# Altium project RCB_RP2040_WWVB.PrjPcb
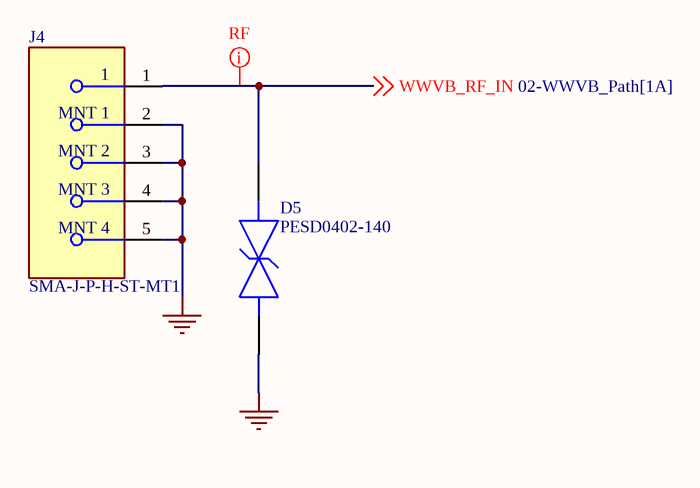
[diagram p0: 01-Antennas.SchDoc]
prjCompanyName: Meta Platforms Technologies, LLC.; prjContactAddress1: 9845 Willows Road NE; prjContactAddress2: Redmond, WA 98052; prjContactEmail: Contact Email; prjContactPhone: (...)-...-....; prjElectricalEngineer: Electical Engineer; prjElectricalEngineerEmail: Electical Engineer Email; prjLayoutEngineer: Layout Engineer; prjLayoutEngineerEmail: Layout Engineer Email; prjMechanicalEngineer: Mechanical Engineer; prjMechanicalEngineerEmail: Mechanical Engineer Email; prjPCB_IPN: 844-XXXXX-XX; prjPCB_Name: PCB Name; prjPCB_Revision: X1; prjProjectName: Project Name; prjSchematic_IPN: 846-XXXXX-XX; prjSchematic_Revision: X1; XprjPCBA_IPN: Set v_prjPCBA_IPN in variant parameters; XprjPCBA_Revision: Set v_prjPCBA_Revision in variant parameters
8 sheets, 224 parts. Net scope: global (net labels, ports and power ports of the same name join across sheets).
Board file: RCB_RP2040_WWVB_V1.PcbDoc
Sheets:
  01-Antennas.SchDoc
  02-WWVB_Path.SchDoc
  03-8A34004_DPLL-1.SchDoc
  04-8A34004_DPLL-2.SchDoc
  05-TCXO_Crystal.SchDoc
  06-RP2040.SchDoc
  07-USB-Prog.SchDoc
  08-Power.SchDoc

## Sheet 01-Antennas.SchDoc
size B; SheetNumber: 1; SheetTotal: 7; SPICEModelCacheELOCFEDZ: <root> / <DocumentId>ELOCFEDZ</DocumentId> / </root>

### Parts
D5  PESD0402-140  [FP-PESD0402-MFG]
J4  SMA-J-P-H-ST-MT1  [FP-SMA-J-P-H-ST-MT1-MFG]

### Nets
GND: D5.1 J4.2(MNT_1) J4.3(MNT_2) J4.4(MNT_3) J4.5(MNT_4)
WWVB_RF_IN: D5.2 J4.1 ; off-sheet WWVB_RF_IN

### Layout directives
net class RF: WWVB_RF_IN

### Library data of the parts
D5 = CMP-08607-000011-1: TVS DIODE 14V 40V 0402; Manufacturer: Littelfuse Inc.; Automotive Grade: Grade 1; Capacitance: 0.25pF; Value: 0.25pF; Direction: Bidirectional; Number Of Channels: 1
J4 = CMP-02754-000007-1: CONN SMA JACK STR 50 OHM SMD; Dielectric Material: PTFE; Voltage Rating: 335V; Body Material: Brass; Center Contact Plating: Gold; Impedance: 50R; Number of Ports: 1; Max Frequency: 20GHz

## Sheet 02-WWVB_Path.SchDoc
size B; SheetNumber: 2; SheetTotal: 8
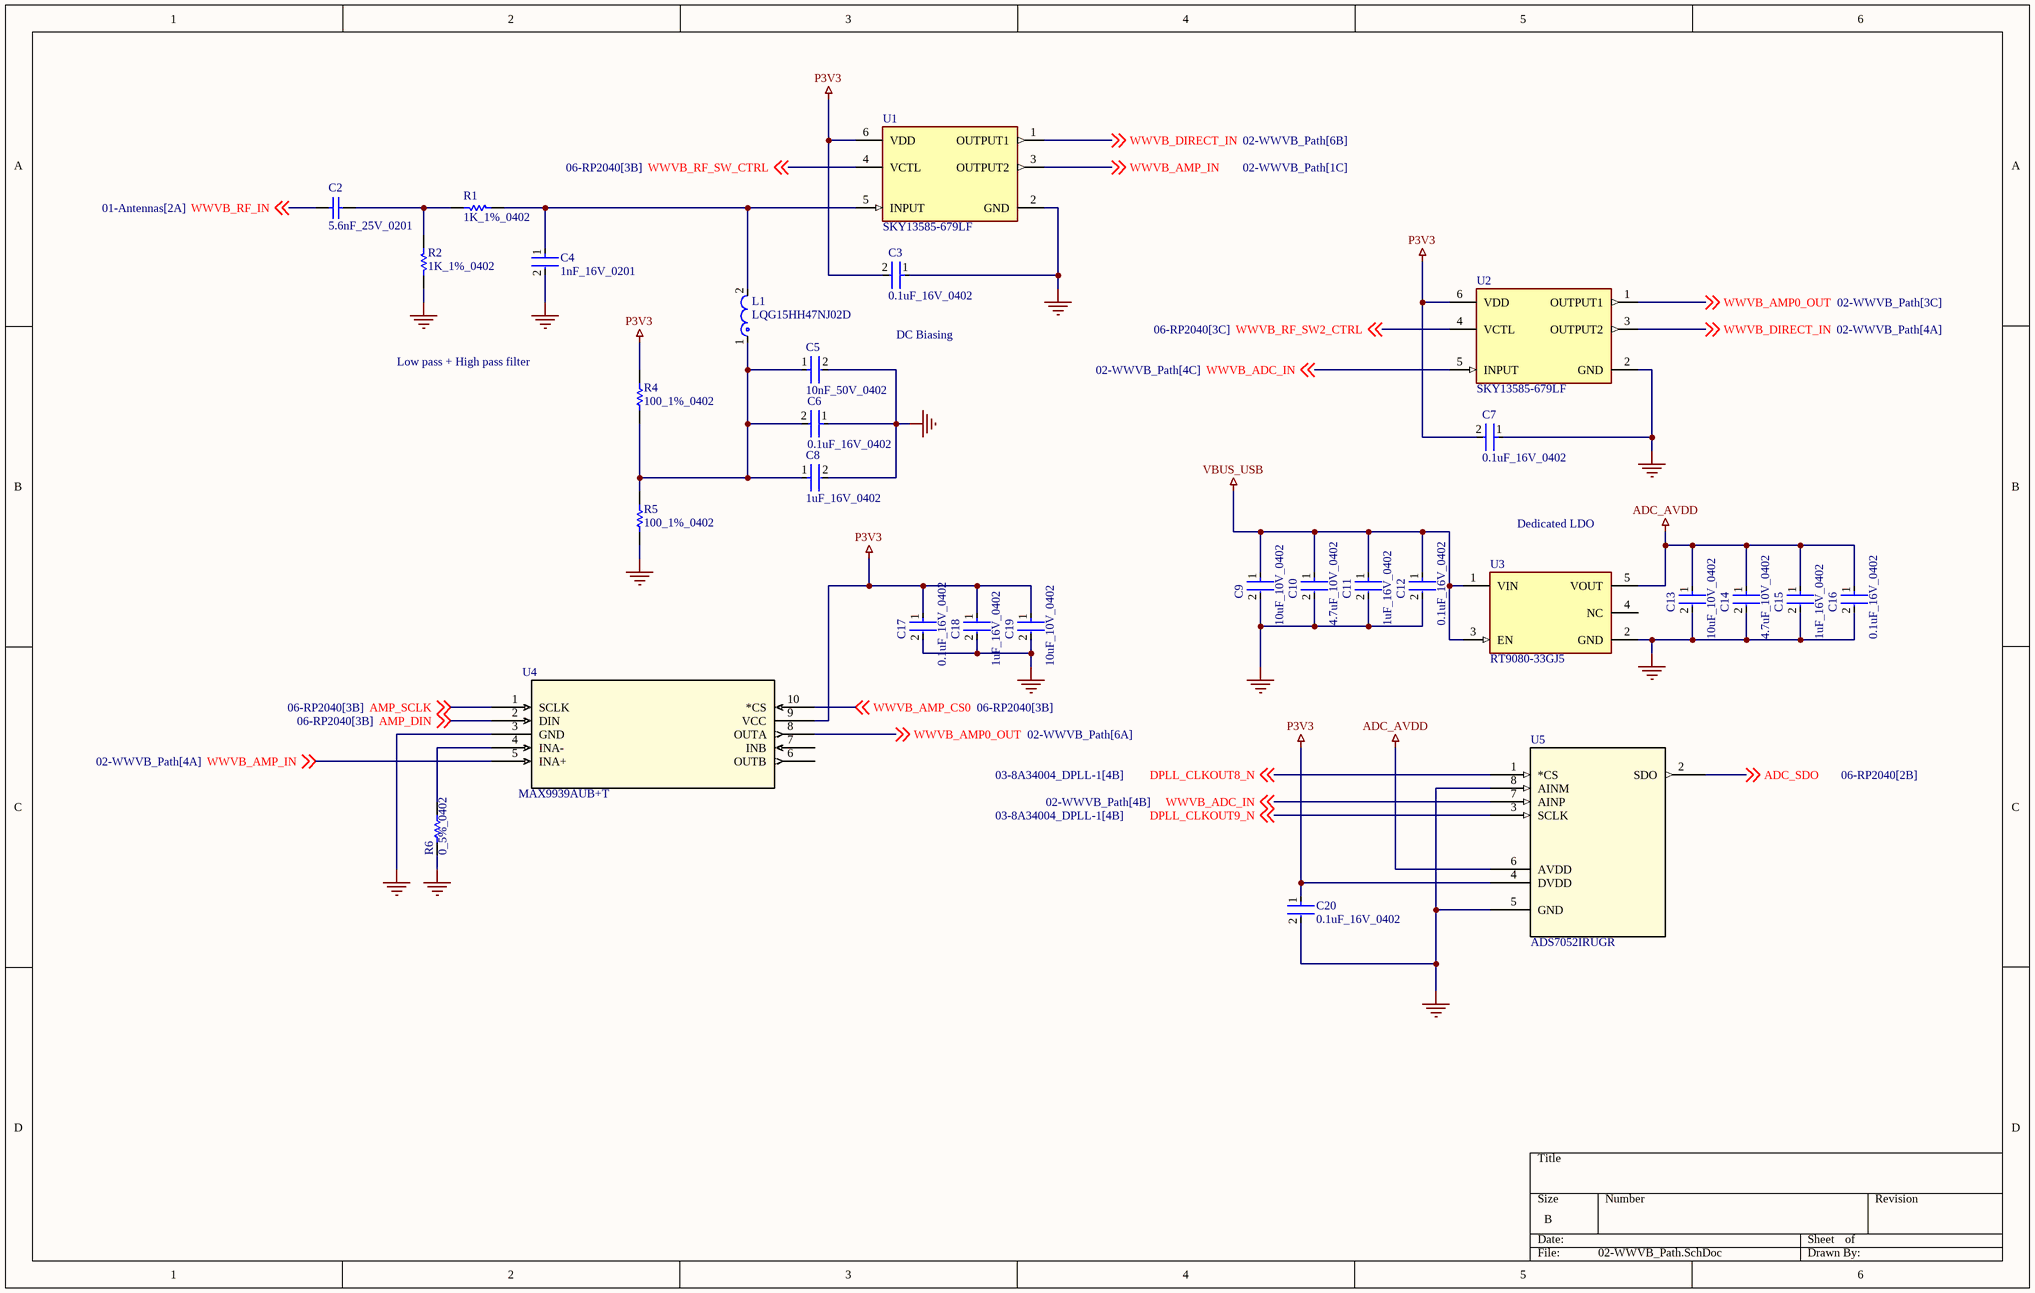
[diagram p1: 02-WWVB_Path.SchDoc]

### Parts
C2  5.6nF_25V_0201  [CAPC0603X33X15ML03T05]
C3  0.1uF_16V_0402  [FP-C0402-BB-MFG]
C4  1nF_16V_0201  [FP-0201-L_0_6_0_09-W_0_3-MFG]
C5  10nF_50V_0402  [FP-CL165-IPC_C]
C6  0.1uF_16V_0402  [FP-C0402-BB-MFG]
C7  0.1uF_16V_0402  [FP-C0402-BB-MFG]
C8  1uF_16V_0402  [FP-0402-L_1_0_0_05-W_0_5-IPC_A]
C9  10uF_10V_0402  [FP-CL05A106MP5NUNC-MFG]
C10  4.7uF_10V_0402  [FP-C1005-050-0_15-MFG]
C11  1uF_16V_0402  [FP-0402-L_1_0_0_05-W_0_5-IPC_A]
C12  0.1uF_16V_0402  [FP-C0402-BB-MFG]
C13  10uF_10V_0402  [FP-CL05A106MP5NUNC-MFG]
C14  4.7uF_10V_0402  [FP-C1005-050-0_15-MFG]
C15  1uF_16V_0402  [FP-0402-L_1_0_0_05-W_0_5-IPC_A]
C16  0.1uF_16V_0402  [FP-C0402-BB-MFG]
C17  0.1uF_16V_0402  [FP-C0402-BB-MFG]
C18  1uF_16V_0402  [FP-0402-L_1_0_0_05-W_0_5-IPC_A]
C19  10uF_10V_0402  [FP-CL05A106MP5NUNC-MFG]
C20  0.1uF_16V_0402  [FP-C0402-BB-MFG]
L1  LQG15HH47NJ02D  [FP-LQG15HH_02-IPC_C]
R1  1K_1%_0402  [RESC1005X40X25NL05T05]
R2  1K_1%_0402  [RESC1005X40X25NL05T05]
R4  100_1%_0402  [RESC1005X40X25ML05T10]
R5  100_1%_0402  [RESC1005X40X25ML05T10]
R6  0_5%_0402  [RESC1005X40X25NL05T10]
U1  SKY13585-679LF  [FP-SKY13585-679LF-MFG]
U2  SKY13585-679LF  [FP-SKY13585-679LF-MFG]
U3  RT9080-33GJ5  [FP-RT9080-33GJ5-IPC_C]
U4  MAX9939AUB+T  [21-0061L_MXM]
U5  ADS7052IRUGR  [RUG8_TEX]

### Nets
ADC_AVDD: C13.1 C14.1 C15.1 C16.1 U3.5(VOUT) U5.6(AVDD)
GND: C3.1 C4.2 C5.2 C6.1 C7.1 C8.2 C9.2 C10.2 C11.2 C12.2 C13.2 C14.2 C15.2 C16.2 C17.2 C18.2 C19.2 C20.2 R2.1 R5.1 R6.1 U1.2(GND) U2.2(GND) U3.2(GND) U4.3(GND) U5.5(GND) U5.8(AINM)
P3V3: C3.2 C7.2 C17.1 C18.1 C19.1 C20.1 R4.2 U1.6(VDD) U2.6(VDD) U4.9(VCC) U5.4(DVDD)
VBUS_USB: C9.1 C10.1 C11.1 C12.1 U3.1(VIN) U3.3(EN)
ADC_SDO: U5.2(SDO) ; off-sheet ADC_SDO
AMP_DIN: U4.2(DIN) ; off-sheet AMP_DIN
AMP_SCLK: U4.1(SCLK) ; off-sheet AMP_SCLK
DPLL_CLKOUT8_N: U5.1(*CS) ; off-sheet DPLL_CLKOUT8_N
DPLL_CLKOUT9_N: U5.3(SCLK) ; off-sheet DPLL_CLKOUT9_N
WWVB_ADC_IN: U2.5(INPUT) U5.7(AINP) ; off-sheet WWVB_ADC_IN
WWVB_AMP0_OUT: U2.1(OUTPUT1) U4.8(OUTA) ; off-sheet WWVB_AMP0_OUT
WWVB_AMP_CS0: U4.10(*CS) ; off-sheet WWVB_AMP_CS0
WWVB_AMP_IN: U1.3(OUTPUT2) U4.5(INA+) ; off-sheet WWVB_AMP_IN
WWVB_DIRECT_IN: U1.1(OUTPUT1) U2.3(OUTPUT2) ; off-sheet WWVB_DIRECT_IN
WWVB_RF_IN: C2.1 ; off-sheet WWVB_RF_IN
WWVB_RF_SW2_CTRL: U2.4(VCTL) ; off-sheet WWVB_RF_SW2_CTRL
WWVB_RF_SW_CTRL: U1.4(VCTL) ; off-sheet WWVB_RF_SW_CTRL
NetC2_2: C2.2 R1.2 R2.2
NetC4_1: C4.1 L1.2 R1.1 U1.5(INPUT)
NetC5_1: C5.1 C6.2 C8.1 L1.1 R4.1 R5.2
NetR6_2: R6.2 U4.4(INA-)

Not connected (* = marked no-connect by the designer): U3 4(NC); U4 6(OUTB) 7(INB)

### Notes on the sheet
- Low pass + High pass filter
- DC Biasing
- Dedicated LDO

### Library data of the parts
C2 = CMP-2010-01745-1: Part Number: MC000322; Manufacturer: Multicomp
C3 C6 C7 C12 C16 C17 C20 = CMP-1034-02068-3: CAP CER 0.1UF 16V 5% X7R 0402; Manufacturer: Kemet; Manufacturer Part Number: C0402C104J4RACTU; Value: 0.10 μF; Temperature Coefficient: 15%; Tolerance: 0.05; Material: Ceramic
C4 = CMP-2010-00182-2: General Purpose Ceramic Capacitor, 0201, 1nF, 10%, X7R, 15%, 16V; Dissipation Factor: 12.5%; Insulation Resistance: 100GR
C5 = CMP-13271-000387-1: Cap Ceramic 10nF 50V X7R ±10% SMD 0402 +125°C Paper T/R
C8 C11 C15 C18 = CMP-14477-000104-2: None; Tolerance: 10%; Voltage Rating: 16V; Dielectric: X5R; Capacitance: 1uF
C9 C13 C19 = CMP-13271-000002-1: CAP CER 10UF 10V X5R 0402; Manufacturer Part Number: CL05A106MP5NUNC; Manufacturer: Samsung; Temperature Coefficient: 15%; Tolerance: 20%; Material: Ceramic
C10 C14 = CMP-2000-05997-2: CAP CER 4.7UF 10V X5R 0402; Dielectric Material: Ceramic; Tolerance: 10%
L1 = CMP-06042-003301-1: Multilayer type Inductor for Automotive 47nH ±5% 0.72Ω 300mA 0402; Max DC Current: 200mA; Core Material: Air; Q Factor: 8; Test Frequency: 100MHz; Self Resonant Frequency: 1GHz; Shielding: Unshielded; DC Resistance (DCR): 720mR
R1 R2 = CMP-2002-08277-1: Manufacturer: Vishay Dale; Part Number: CRCW04021K00FKTD
R4 R5 = CMP-2002-06458-1: Part Number: ERJ-U02F1000X; Manufacturer: Panasonic
R6 = CMP-2002-06457-1: Manufacturer: Panasonic; Part Number: ERJ-U020R00X
U1 U2 = CMP-85923-000009-1: IC RF SWITCH SPDT 6GHZ 6MLPD; Insertion Loss: 0.5dB; Impedance: 50R; IIP3: 56dBm; Test Frequency: 2.5GHz
U3 = CMP-79890-000003-1: IC REG LIN 3.3V 600MA TSOT23-5; Power Supply Rejection Ratio (PSRR): 75dB; Output Type: Fixed; Max Input Voltage: 5.5V; Dropout Voltage: 530mV; Output Configuration: Positive; Quiescent Current: 4uA; Number of Regulators: 1
U4 = MAX9939AUB+T: No Description Available; Mfr_Name: Analog Devices Inc
U5 = ADS7052IRUGR: No Description Available; Mfr_Name: Texas Instruments

## Sheet 03-8A34004_DPLL-1.SchDoc
size B; SheetNumber: 3; SheetTotal: 8
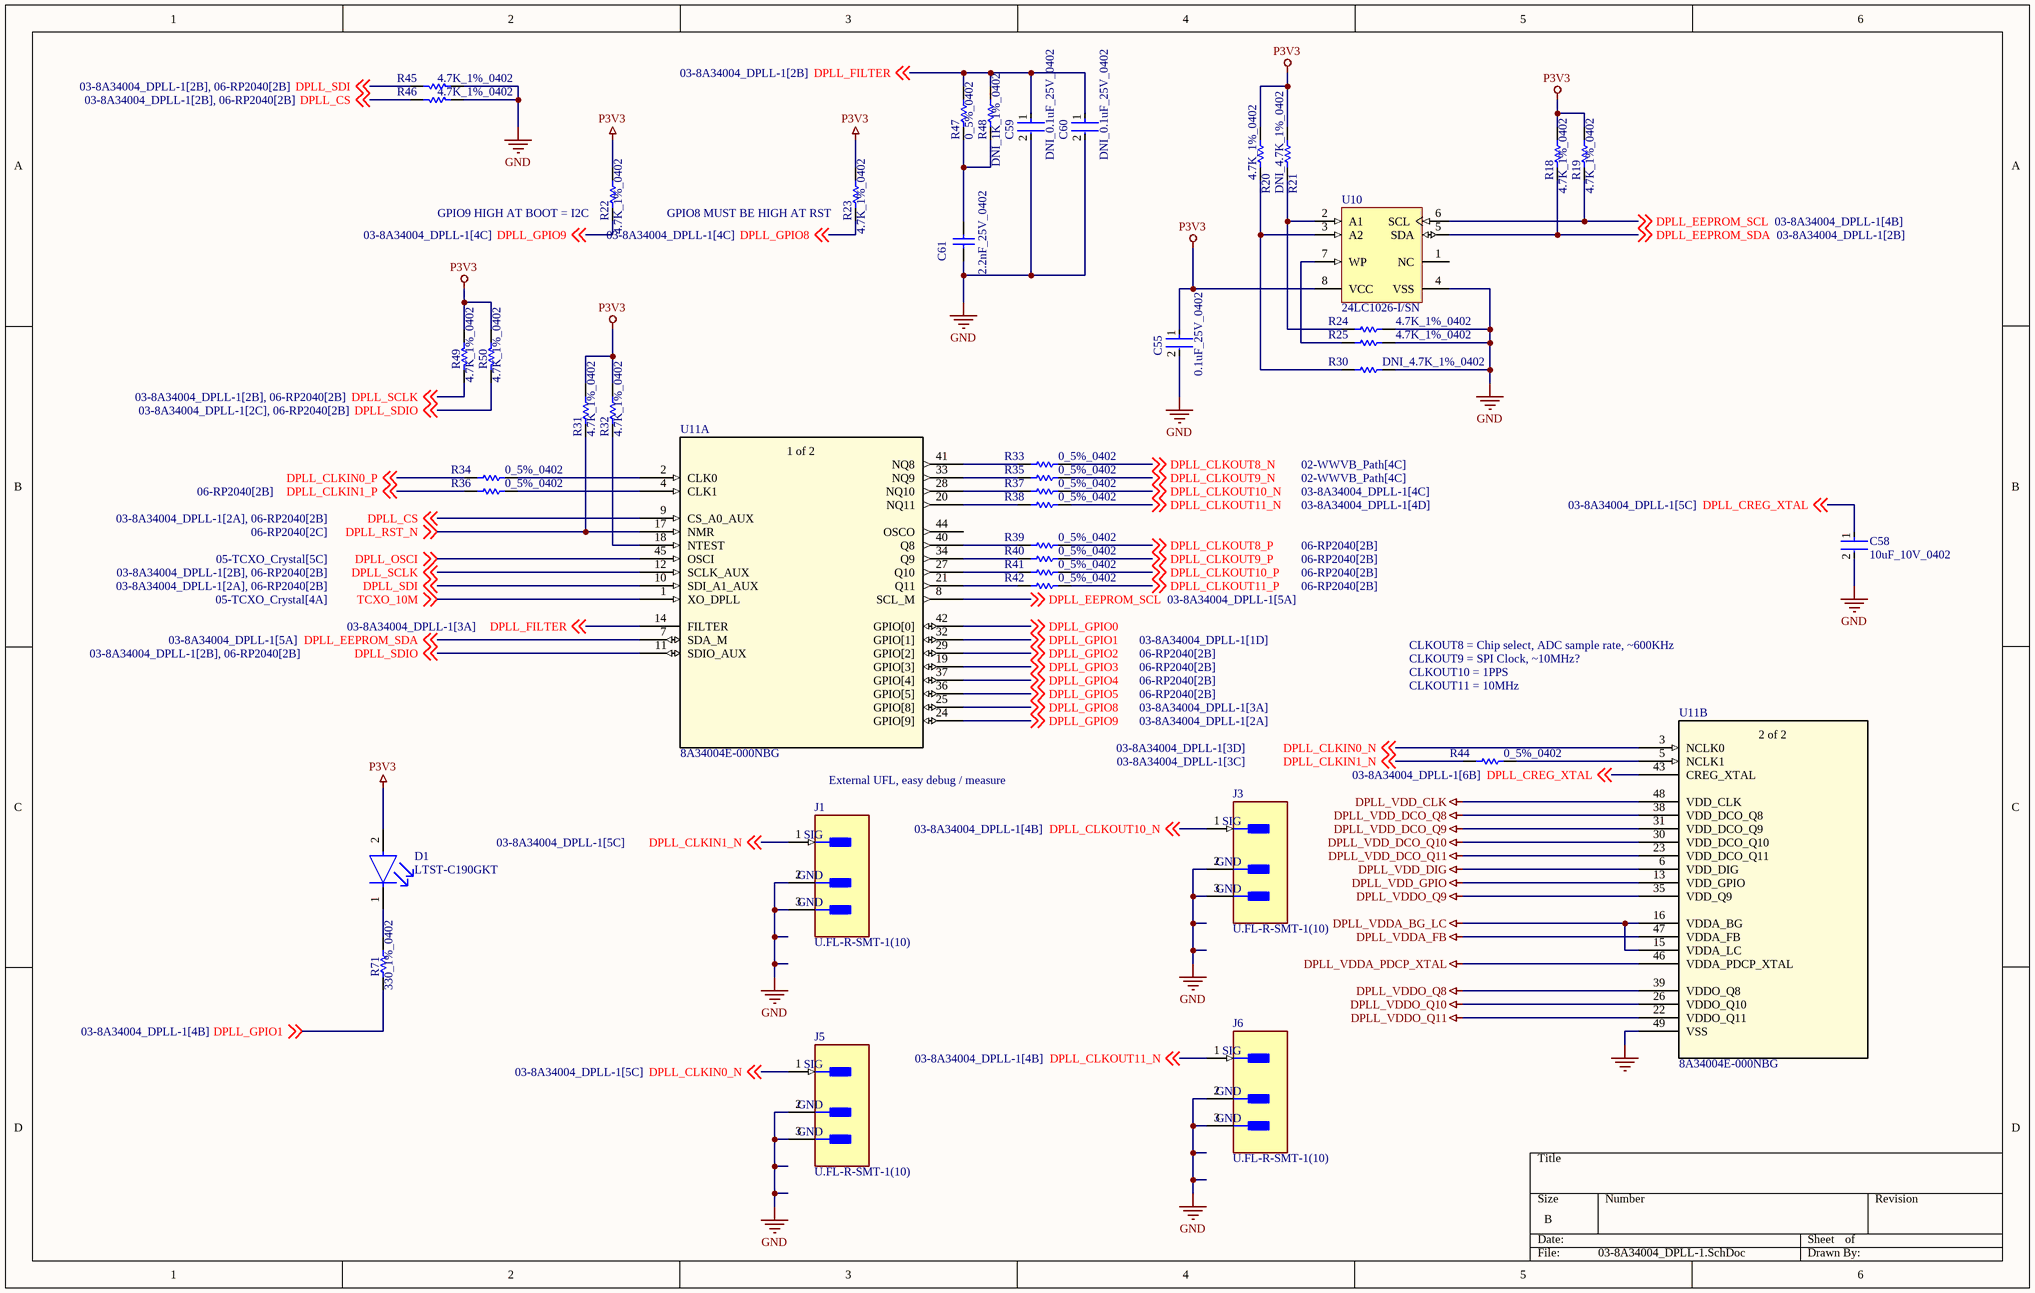
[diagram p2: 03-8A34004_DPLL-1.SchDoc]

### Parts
C55  0.1uF_25V_0402  [FP-0402-L_1_0_1-W_0_5_0_1-IPC_C]
C58  10uF_10V_0402  [FP-CL05A106MP5NUNC-MFG]
C59  DNI_0.1uF_25V_0402  [FP-0402-L_1_0_1-W_0_5_0_1-IPC_C]  (no BOM)
C60  DNI_0.1uF_25V_0402  [FP-0402-L_1_0_1-W_0_5_0_1-IPC_C]  (no BOM)
C61  2.2nF_25V_0402  [CAPC1005X56X25LL10T15]
D1  LTST-C190GKT  [FP-LTST-C190GKT-MFG]
J1  U.FL-R-SMT-1(10)  [FP-U_FL-R-SMT-1_10-MFG]
J3  U.FL-R-SMT-1(10)  [FP-U_FL-R-SMT-1_10-MFG]
J5  U.FL-R-SMT-1(10)  [FP-U_FL-R-SMT-1_10-MFG]
J6  U.FL-R-SMT-1(10)  [FP-U_FL-R-SMT-1_10-MFG]
R18  4.7K_1%_0402  [RESC1005X40X25NL10T10]
R19  4.7K_1%_0402  [RESC1005X40X25NL10T10]
R20  4.7K_1%_0402  [RESC1005X40X25NL10T10]
R21  DNI_4.7K_1%_0402  [RESC1005X40X25NL10T10]  (no BOM)
R22  4.7K_1%_0402  [RESC1005X40X25NL10T10]
R23  4.7K_1%_0402  [RESC1005X40X25NL10T10]
R24  4.7K_1%_0402  [RESC1005X40X25NL10T10]
R25  4.7K_1%_0402  [RESC1005X40X25NL10T10]
R30  DNI_4.7K_1%_0402  [RESC1005X40X25NL10T10]  (no BOM)
R31  4.7K_1%_0402  [RESC1005X40X25NL10T10]
R32  4.7K_1%_0402  [RESC1005X40X25NL10T10]
R33  0_5%_0402  [RESC1005X40X25NL05T10]
R34  0_5%_0402  [RESC1005X40X25NL05T10]
R35  0_5%_0402  [RESC1005X40X25NL05T10]
R36  0_5%_0402  [RESC1005X40X25NL05T10]
R37  0_5%_0402  [RESC1005X40X25NL05T10]
R38  0_5%_0402  [RESC1005X40X25NL05T10]
R39  0_5%_0402  [RESC1005X40X25NL05T10]
R40  0_5%_0402  [RESC1005X40X25NL05T10]
R41  0_5%_0402  [RESC1005X40X25NL05T10]
R42  0_5%_0402  [RESC1005X40X25NL05T10]
R44  0_5%_0402  [RESC1005X40X25NL05T10]
R45  4.7K_1%_0402  [RESC1005X40X25NL10T10]
R46  4.7K_1%_0402  [RESC1005X40X25NL10T10]
R47  0_5%_0402  [RESC1005X40X25LL10T10]
R48  DNI_1K_1%_0402  [RESC1005X40X25NL05T05]  (no BOM)
R49  4.7K_1%_0402  [RESC1005X40X25NL10T10]
R50  4.7K_1%_0402  [RESC1005X40X25NL10T10]
R71  330_1%_0402  [RESC1005X40X25NL10T10]
U10  24LC1026-I/SN  [MCHP-SOIC-SN8_N]
U11  8A34004E-000NBG  [NBG48P1_REN]  (parts A,B of 2)

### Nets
DPLL_VDD_CLK: U11.48(VDD_CLK)
DPLL_VDD_DCO_Q8: U11.38(VDD_DCO_Q8)
DPLL_VDD_DCO_Q9: U11.31(VDD_DCO_Q9)
DPLL_VDD_DCO_Q10: U11.30(VDD_DCO_Q10)
DPLL_VDD_DCO_Q11: U11.23(VDD_DCO_Q11)
DPLL_VDD_DIG: U11.6(VDD_DIG)
DPLL_VDD_GPIO: U11.13(VDD_GPIO)
DPLL_VDDA_BG_LC: U11.15(VDDA_LC) U11.16(VDDA_BG)
DPLL_VDDA_FB: U11.47(VDDA_FB)
DPLL_VDDA_PDCP_XTAL: U11.46(VDDA_PDCP_XTAL)
DPLL_VDDO_Q8: U11.39(VDDO_Q8)
DPLL_VDDO_Q9: U11.35(VDD_Q9)
DPLL_VDDO_Q10: U11.26(VDDO_Q10)
DPLL_VDDO_Q11: U11.22(VDDO_Q11)
GND: C55.2 C58.2 C59.2 C60.2 C61.1 J1.2(GND) J1.3(GND) J3.2(GND) J3.3(GND) J5.2(GND) J5.3(GND) J6.2(GND) J6.3(GND) R24.1 R25.1 R30.2 R45.2 R46.2 U10.4(VSS) U11.49(VSS)
P3V3: C55.1 D1.2(A) R18.1 R19.1 R20.2 R21.2 R22.1 R23.1 R31.2 R32.2 R49.2 R50.2 U10.8(VCC)
DPLL_CLKIN0_N: J5.1(SIG) U11.3(NCLK0) ; off-sheet DPLL_CLKIN0_N
DPLL_CLKIN0_P: R34.1 ; off-sheet DPLL_CLKIN0_P
DPLL_CLKIN1_N: J1.1(SIG) R44.1 ; off-sheet DPLL_CLKIN1_N
DPLL_CLKIN1_P: R36.1 ; off-sheet DPLL_CLKIN1_P
DPLL_CLKOUT8_N: R33.2 ; off-sheet DPLL_CLKOUT8_N
DPLL_CLKOUT8_P: R39.2 ; off-sheet DPLL_CLKOUT8_P
DPLL_CLKOUT9_N: R35.2 ; off-sheet DPLL_CLKOUT9_N
DPLL_CLKOUT9_P: R40.2 ; off-sheet DPLL_CLKOUT9_P
DPLL_CLKOUT10_N: J3.1(SIG) R37.2 ; off-sheet DPLL_CLKOUT10_N
DPLL_CLKOUT10_P: R41.2 ; off-sheet DPLL_CLKOUT10_P
DPLL_CLKOUT11_N: J6.1(SIG) R38.2 ; off-sheet DPLL_CLKOUT11_N
DPLL_CLKOUT11_P: R42.2 ; off-sheet DPLL_CLKOUT11_P
DPLL_CREG_XTAL: C58.1 U11.43(CREG_XTAL) ; off-sheet DPLL_CREG_XTAL
DPLL_CS: R46.1 U11.9(CS_A0_AUX) ; off-sheet DPLL_CS
DPLL_EEPROM_SCL: R19.2 U10.6(SCL) U11.8(SCL_M) ; off-sheet DPLL_EEPROM_SCL
DPLL_EEPROM_SDA: R18.2 U10.5(SDA) U11.7(SDA_M) ; off-sheet DPLL_EEPROM_SDA
DPLL_FILTER: C59.1 C60.1 R47.2 R48.2 U11.14(FILTER) ; off-sheet DPLL_FILTER
DPLL_GPIO0: U11.42(GPIO[0]) ; off-sheet DPLL_GPIO0
DPLL_GPIO1: R71.1 U11.32(GPIO[1]) ; off-sheet DPLL_GPIO1
DPLL_GPIO2: U11.29(GPIO[2]) ; off-sheet DPLL_GPIO2
DPLL_GPIO3: U11.19(GPIO[3]) ; off-sheet DPLL_GPIO3
DPLL_GPIO4: U11.37(GPIO[4]) ; off-sheet DPLL_GPIO4
DPLL_GPIO5: U11.36(GPIO[5]) ; off-sheet DPLL_GPIO5
DPLL_GPIO8: R23.2 U11.25(GPIO[8]) ; off-sheet DPLL_GPIO8
DPLL_GPIO9: R22.2 U11.24(GPIO[9]) ; off-sheet DPLL_GPIO9
DPLL_OSCI: U11.45(OSCI) ; off-sheet DPLL_OSCI
DPLL_RST_N: R31.1 U11.17(NMR) ; off-sheet DPLL_RST_N
DPLL_SCLK: R49.1 U11.12(SCLK_AUX) ; off-sheet DPLL_SCLK
DPLL_SDI: R45.1 U11.10(SDI_A1_AUX) ; off-sheet DPLL_SDI
DPLL_SDIO: R50.1 U11.11(SDIO_AUX) ; off-sheet DPLL_SDIO
TCXO_10M: U11.1(XO_DPLL) ; off-sheet TCXO_10M
NetC61_2: C61.2 R47.1 R48.1
NetD1_1: D1.1(C) R71.2
NetR20_1: R20.1 R30.1 U10.3(A2)
NetR21_1: R21.1 R24.2 U10.2(A1)
NetR25_2: R25.2 U10.7(WP)
NetR32_1: R32.1 U11.18(NTEST)
NetR33_1: R33.1 U11.41(NQ8)
NetR34_2: R34.2 U11.2(CLK0)
NetR35_1: R35.1 U11.33(NQ9)
NetR36_2: R36.2 U11.4(CLK1)
NetR37_1: R37.1 U11.28(NQ10)
NetR38_1: R38.1 U11.20(NQ11)
NetR39_1: R39.1 U11.40(Q8)
NetR40_1: R40.1 U11.34(Q9)
NetR41_1: R41.1 U11.27(Q10)
NetR42_1: R42.1 U11.21(Q11)
NetR44_2: R44.2 U11.5(NCLK1)

Not connected (* = marked no-connect by the designer): U10 1(NC); U11 44(OSCO)

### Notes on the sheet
- (near R22) GPIO9 HIGH AT BOOT = I2C
- GPIO8 MUST BE HIGH AT RST
- CLKOUT8 = Chip select, ADC sample rate, ~600KHz
- CLKOUT9 = SPI Clock,
  0MHz?
- CLKOUT10 = 1PPS
- CLKOUT11 = 10MHz
- External UFL, easy debug / measure

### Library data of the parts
C55 C59 C60 = CMP-2008-02519-2: General Purpose Ceramic Capacitor, 0402, 100nF, 10%, X7R, 15%, 25V
C58 = CMP-13271-000002-1: as C9 on sheet 02-WWVB_Path
C61 = CMP-2008-02907-1: Manufacturer: AVX Interconnect / Elco; Part Number: 04025C222JAT2A
D1 = CMP-22017-000005-2: LED GREEN CLEAR CHIP SMD; Dominant Wavelength: 569nm; Reverse Voltage: 5V; Lens Color: Colorless; Viewing Angle: 130°; Voltage: 2V; Forward Current: 30mA; Power Dissipation: 100mW; Luminous Intensity: 6mcd; Number of LEDs: 1; Forward Voltage: 2.1V; Wavelength: 565nm; Test Current: 10mA
J1 J3 J5 J6 = CMP-2000-05152-3: CONN U.FL RCPT STR 50 OHM SMD; Max Frequency: 6GHz; Connector Type: Coaxial; Body Plating: Silver; Body Material: Bronze; Impedance: 50R; Dielectric Material: Polymer; Insulation Resistance: 500MR; Gender: Male
R18-R25 R30-R32 R45 R46 R49 R50 = CMP-2002-05217-1: Manufacturer: Bourns; Part Number: CR0402-FX-4701GLF
R33-R42 R44 = CMP-2002-06457-1: as R6 on sheet 02-WWVB_Path
R47 = CMP-2002-04569-1: Manufacturer: KOA Speer; Part Number: RK73Z1ETTP
R48 = CMP-2002-08277-1: as R1 on sheet 02-WWVB_Path
R71 = CMP-2002-05853-1: Manufacturer: Panasonic; Part Number: ERA-2AED331X
U10 = CMP-0159-01024-1: 1024K bits I2C™ Serial EEPROM, 2.5 to 5.5 V, 400 kHz, -40 to 85 degC, 8-pin SOIC (SN8), Tube; Manufacturer: Microchip
U11 = 8A34004E-000NBG: No Description Available; Mfr_Name: Renesas Electronics

## Sheet 04-8A34004_DPLL-2.SchDoc
size B; SheetNumber: 4; SheetTotal: 8
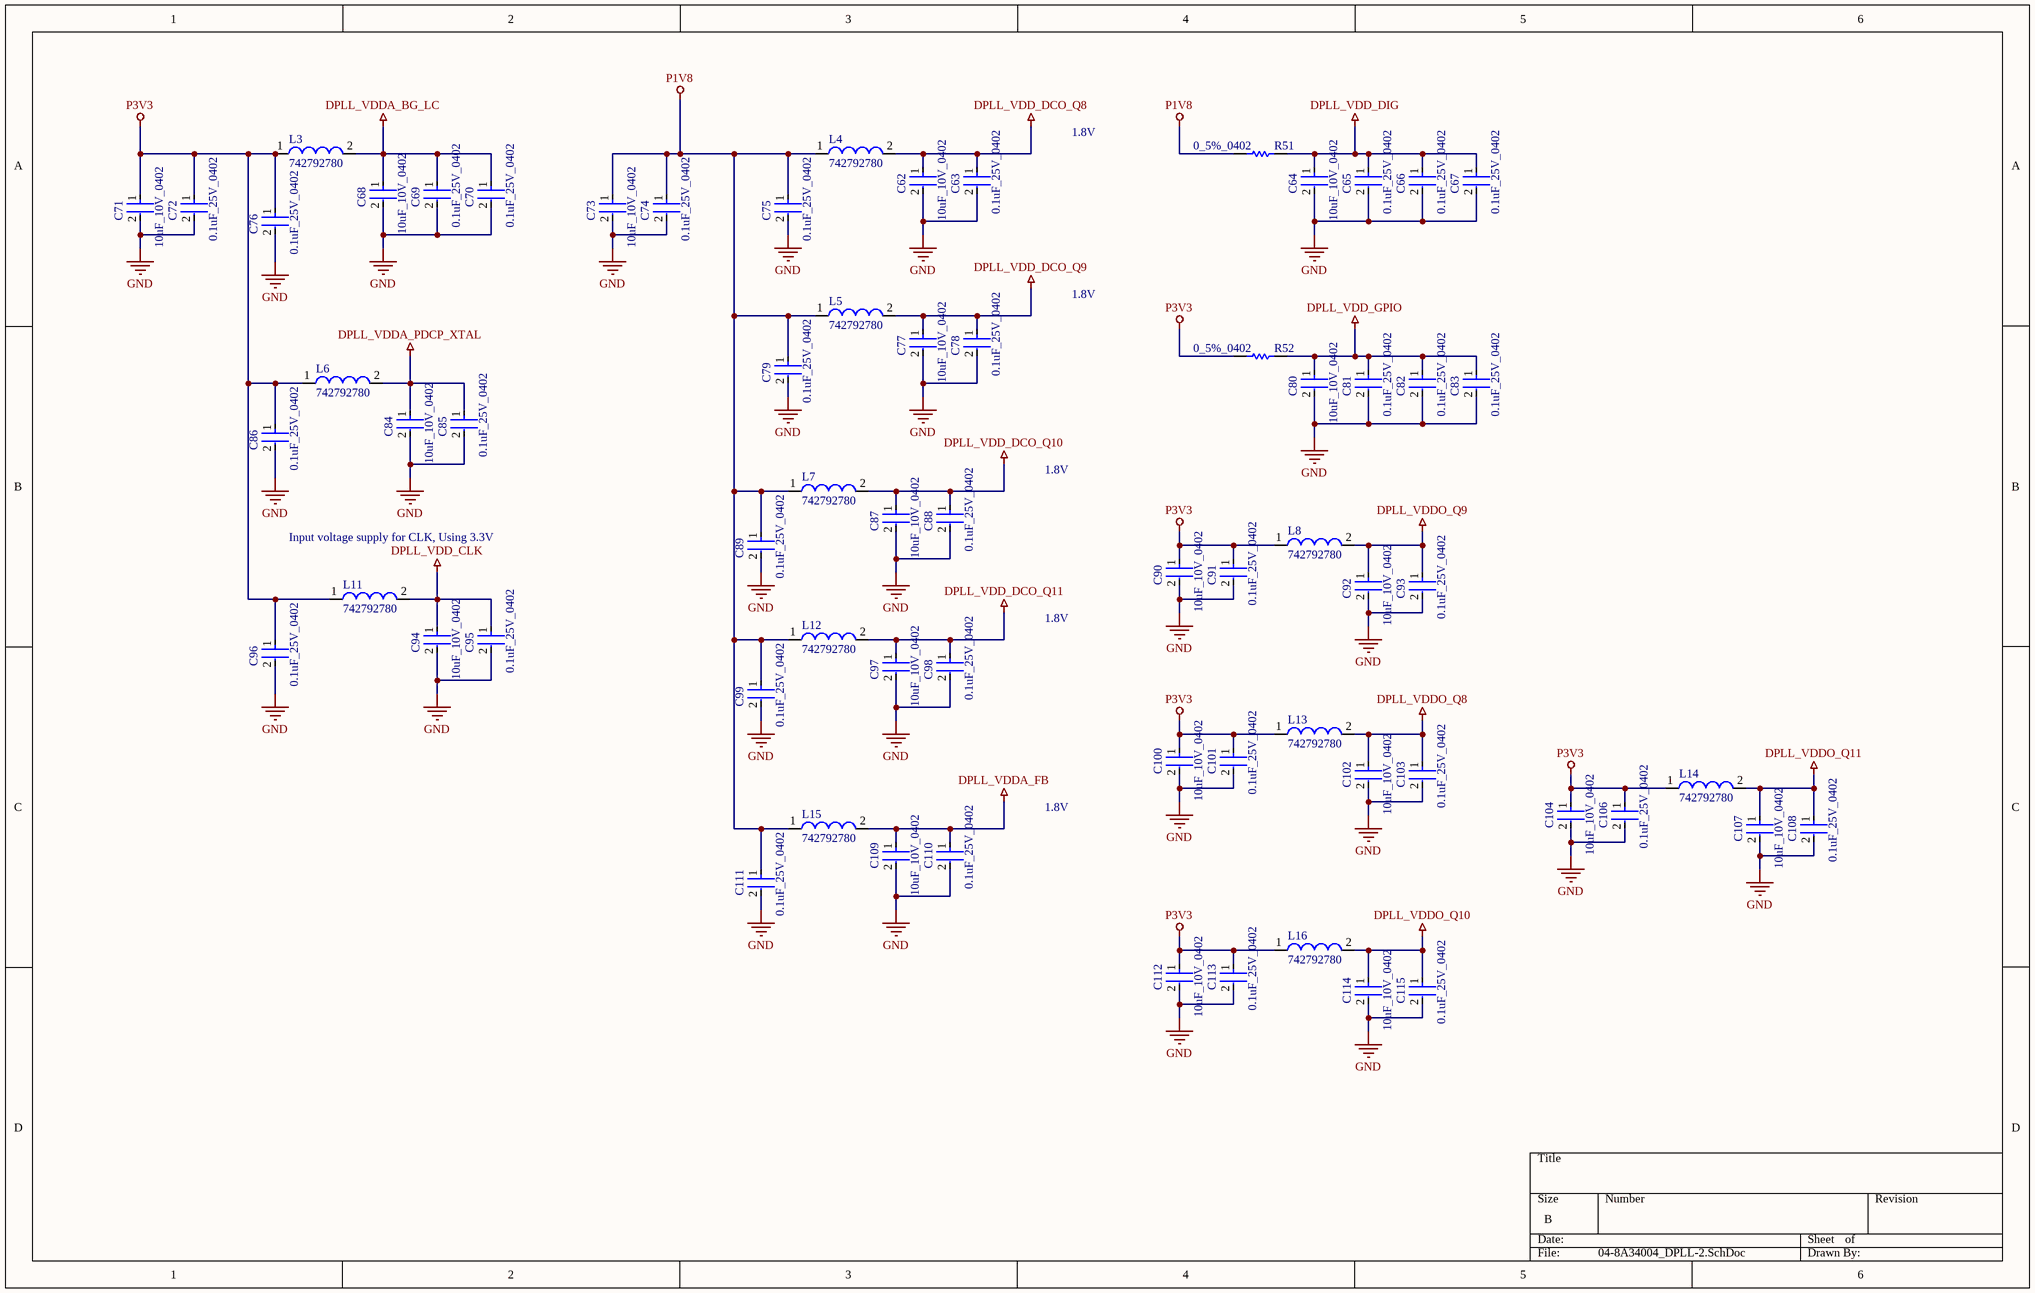
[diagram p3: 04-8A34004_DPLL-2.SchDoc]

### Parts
C62  10uF_10V_0402  [FP-CL05A106MP5NUNC-MFG]
C63  0.1uF_25V_0402  [FP-0402-L_1_0_1-W_0_5_0_1-IPC_C]
C64  10uF_10V_0402  [FP-CL05A106MP5NUNC-MFG]
C65  0.1uF_25V_0402  [FP-0402-L_1_0_1-W_0_5_0_1-IPC_C]
C66  0.1uF_25V_0402  [FP-0402-L_1_0_1-W_0_5_0_1-IPC_C]
C67  0.1uF_25V_0402  [FP-0402-L_1_0_1-W_0_5_0_1-IPC_C]
C68  10uF_10V_0402  [FP-CL05A106MP5NUNC-MFG]
C69  0.1uF_25V_0402  [FP-0402-L_1_0_1-W_0_5_0_1-IPC_C]
C70  0.1uF_25V_0402  [FP-0402-L_1_0_1-W_0_5_0_1-IPC_C]
C71  10uF_10V_0402  [FP-CL05A106MP5NUNC-MFG]
C72  0.1uF_25V_0402  [FP-0402-L_1_0_1-W_0_5_0_1-IPC_C]
C73  10uF_10V_0402  [FP-CL05A106MP5NUNC-MFG]
C74  0.1uF_25V_0402  [FP-0402-L_1_0_1-W_0_5_0_1-IPC_C]
C75  0.1uF_25V_0402  [FP-0402-L_1_0_1-W_0_5_0_1-IPC_C]
C76  0.1uF_25V_0402  [FP-0402-L_1_0_1-W_0_5_0_1-IPC_C]
C77  10uF_10V_0402  [FP-CL05A106MP5NUNC-MFG]
C78  0.1uF_25V_0402  [FP-0402-L_1_0_1-W_0_5_0_1-IPC_C]
C79  0.1uF_25V_0402  [FP-0402-L_1_0_1-W_0_5_0_1-IPC_C]
C80  10uF_10V_0402  [FP-CL05A106MP5NUNC-MFG]
C81  0.1uF_25V_0402  [FP-0402-L_1_0_1-W_0_5_0_1-IPC_C]
C82  0.1uF_25V_0402  [FP-0402-L_1_0_1-W_0_5_0_1-IPC_C]
C83  0.1uF_25V_0402  [FP-0402-L_1_0_1-W_0_5_0_1-IPC_C]
C84  10uF_10V_0402  [FP-CL05A106MP5NUNC-MFG]
C85  0.1uF_25V_0402  [FP-0402-L_1_0_1-W_0_5_0_1-IPC_C]
C86  0.1uF_25V_0402  [FP-0402-L_1_0_1-W_0_5_0_1-IPC_C]
C87  10uF_10V_0402  [FP-CL05A106MP5NUNC-MFG]
C88  0.1uF_25V_0402  [FP-0402-L_1_0_1-W_0_5_0_1-IPC_C]
C89  0.1uF_25V_0402  [FP-0402-L_1_0_1-W_0_5_0_1-IPC_C]
C90  10uF_10V_0402  [FP-CL05A106MP5NUNC-MFG]
C91  0.1uF_25V_0402  [FP-0402-L_1_0_1-W_0_5_0_1-IPC_C]
C92  10uF_10V_0402  [FP-CL05A106MP5NUNC-MFG]
C93  0.1uF_25V_0402  [FP-0402-L_1_0_1-W_0_5_0_1-IPC_C]
C94  10uF_10V_0402  [FP-CL05A106MP5NUNC-MFG]
C95  0.1uF_25V_0402  [FP-0402-L_1_0_1-W_0_5_0_1-IPC_C]
C96  0.1uF_25V_0402  [FP-0402-L_1_0_1-W_0_5_0_1-IPC_C]
C97  10uF_10V_0402  [FP-CL05A106MP5NUNC-MFG]
C98  0.1uF_25V_0402  [FP-0402-L_1_0_1-W_0_5_0_1-IPC_C]
C99  0.1uF_25V_0402  [FP-0402-L_1_0_1-W_0_5_0_1-IPC_C]
C100  10uF_10V_0402  [FP-CL05A106MP5NUNC-MFG]
C101  0.1uF_25V_0402  [FP-0402-L_1_0_1-W_0_5_0_1-IPC_C]
C102  10uF_10V_0402  [FP-CL05A106MP5NUNC-MFG]
C103  0.1uF_25V_0402  [FP-0402-L_1_0_1-W_0_5_0_1-IPC_C]
C104  10uF_10V_0402  [FP-CL05A106MP5NUNC-MFG]
C106  0.1uF_25V_0402  [FP-0402-L_1_0_1-W_0_5_0_1-IPC_C]
C107  10uF_10V_0402  [FP-CL05A106MP5NUNC-MFG]
C108  0.1uF_25V_0402  [FP-0402-L_1_0_1-W_0_5_0_1-IPC_C]
C109  10uF_10V_0402  [FP-CL05A106MP5NUNC-MFG]
C110  0.1uF_25V_0402  [FP-0402-L_1_0_1-W_0_5_0_1-IPC_C]
C111  0.1uF_25V_0402  [FP-0402-L_1_0_1-W_0_5_0_1-IPC_C]
C112  10uF_10V_0402  [FP-CL05A106MP5NUNC-MFG]
C113  0.1uF_25V_0402  [FP-0402-L_1_0_1-W_0_5_0_1-IPC_C]
C114  10uF_10V_0402  [FP-CL05A106MP5NUNC-MFG]
C115  0.1uF_25V_0402  [FP-0402-L_1_0_1-W_0_5_0_1-IPC_C]
L3  742792780  [SMD-0402]
L4  742792780  [SMD-0402]
L5  742792780  [SMD-0402]
L6  742792780  [SMD-0402]
L7  742792780  [SMD-0402]
L8  742792780  [SMD-0402]
L11  742792780  [SMD-0402]
L12  742792780  [SMD-0402]
L13  742792780  [SMD-0402]
L14  742792780  [SMD-0402]
L15  742792780  [SMD-0402]
L16  742792780  [SMD-0402]
R51  0_5%_0402  [RESC1005X40X25LL10T10]
R52  0_5%_0402  [RESC1005X40X25LL10T10]

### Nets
DPLL_VDD_CLK: C94.1 C95.1 L11.2
DPLL_VDD_DCO_Q8: C62.1 C63.1 L4.2
DPLL_VDD_DCO_Q9: C77.1 C78.1 L5.2
DPLL_VDD_DCO_Q10: C87.1 C88.1 L7.2
DPLL_VDD_DCO_Q11: C97.1 C98.1 L12.2
DPLL_VDD_DIG: C64.1 C65.1 C66.1 C67.1 R51.2
DPLL_VDD_GPIO: C80.1 C81.1 C82.1 C83.1 R52.2
DPLL_VDDA_BG_LC: C68.1 C69.1 C70.1 L3.2
DPLL_VDDA_FB: C109.1 C110.1 L15.2
DPLL_VDDA_PDCP_XTAL: C84.1 C85.1 L6.2
DPLL_VDDO_Q8: C102.1 C103.1 L13.2
DPLL_VDDO_Q9: C92.1 C93.1 L8.2
DPLL_VDDO_Q10: C114.1 C115.1 L16.2
DPLL_VDDO_Q11: C107.1 C108.1 L14.2
GND: C62.2 C63.2 C64.2 C65.2 C66.2 C67.2 C68.2 C69.2 C70.2 C71.2 C72.2 C73.2 C74.2 C75.2 C76.2 C77.2 C78.2 C79.2 C80.2 C81.2 C82.2 C83.2 C84.2 C85.2 C86.2 C87.2 C88.2 C89.2 C90.2 C91.2 C92.2 C93.2 C94.2 C95.2 C96.2 C97.2 C98.2 C99.2 C100.2 C101.2 C102.2 C103.2 C104.2 C106.2 C107.2 C108.2 C109.2 C110.2 C111.2 C112.2 C113.2 C114.2 C115.2
P1V8: C73.1 C74.1 C75.1 C79.1 C89.1 C99.1 C111.1 L4.1 L5.1 L7.1 L12.1 L15.1 R51.1
P3V3: C71.1 C72.1 C76.1 C86.1 C90.1 C91.1 C96.1 C100.1 C101.1 C104.1 C106.1 C112.1 C113.1 L3.1 L6.1 L8.1 L11.1 L13.1 L14.1 L16.1 R52.1

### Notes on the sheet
- 1.8V
- Input voltage supply for CLK, Using 3.3V

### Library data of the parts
C62 C64 C68 C71 C73 C77 C80 C84 C87 C90 C92 C94 C97 C100 C102 C104 C107 C109 C112 C114 = CMP-13271-000002-1: as C9 on sheet 02-WWVB_Path
C63 C65-C67 C69 C70 C72 C74-C76 C78 C79 C81-C83 C85 C86 C88 C89 C91 C93 C95 C96 C98 C99 C101 C103 C106 C108 C110 C111 C113 C115 = CMP-2008-02519-2: as C55 on sheet 03-8A34004_DPLL-1
L3-L8 L11-L16 = CMP-0220-00137-1: SMD EMI Suppression Ferrite Bead WE-CBF, Z = 220 Ohm; Impedance: 220 Ohm
R51 R52 = CMP-2002-04569-1: as R47 on sheet 03-8A34004_DPLL-1

## Sheet 05-TCXO_Crystal.SchDoc
size B; SheetNumber: 4; SheetTotal: 7
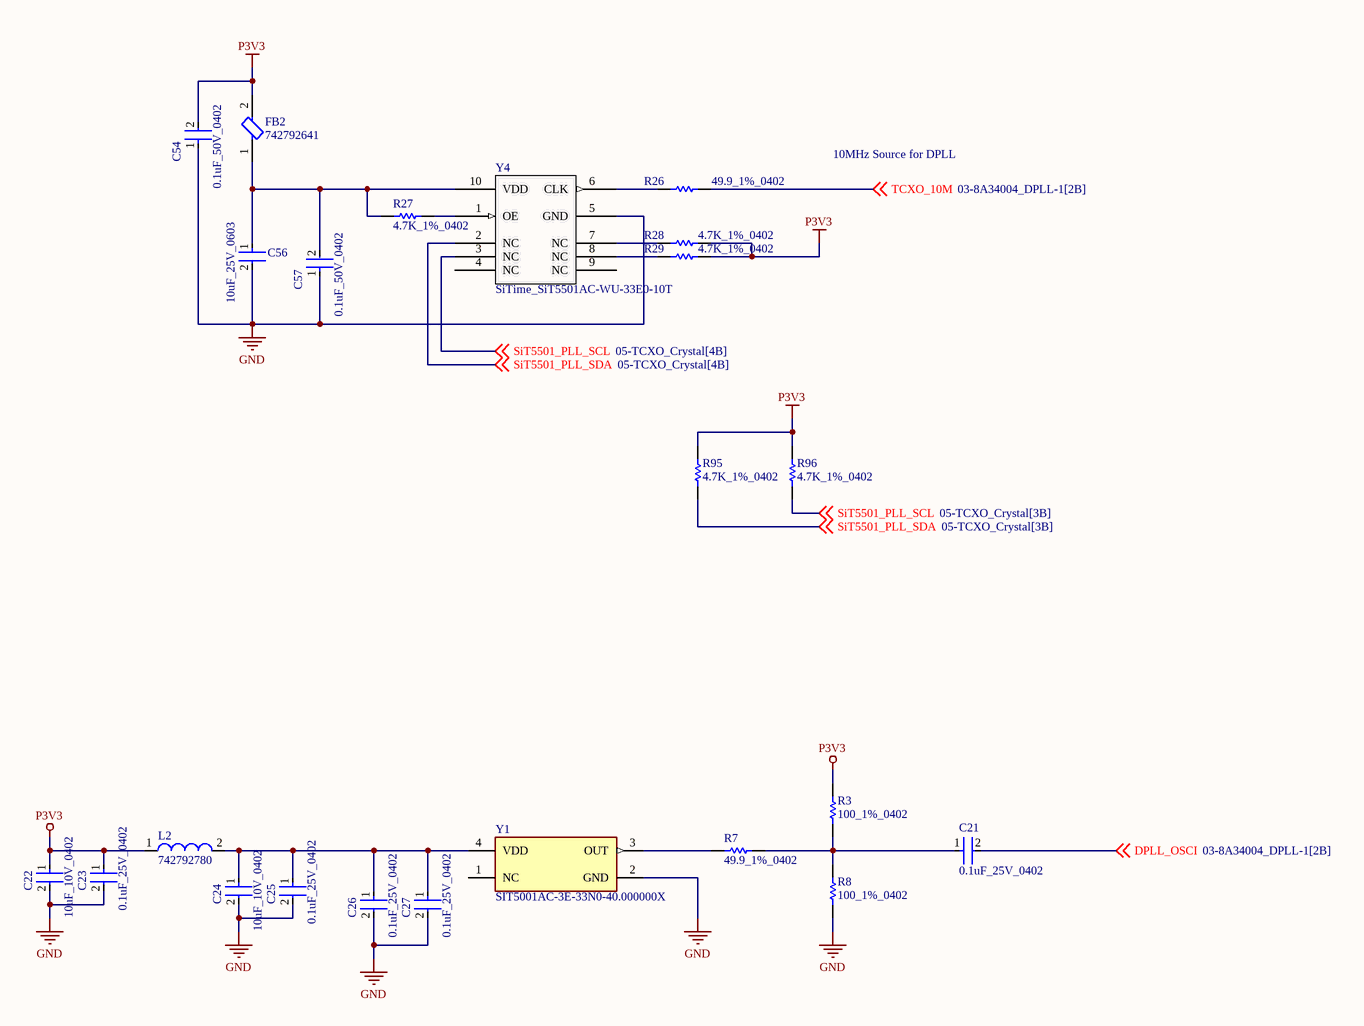
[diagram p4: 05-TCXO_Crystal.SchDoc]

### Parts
C21  0.1uF_25V_0402  [FP-0402-L_1_0_1-W_0_5_0_1-IPC_C]
C22  10uF_10V_0402  [FP-CL05A106MP5NUNC-MFG]
C23  0.1uF_25V_0402  [FP-0402-L_1_0_1-W_0_5_0_1-IPC_C]
C24  10uF_10V_0402  [FP-CL05A106MP5NUNC-MFG]
C25  0.1uF_25V_0402  [FP-0402-L_1_0_1-W_0_5_0_1-IPC_C]
C26  0.1uF_25V_0402  [FP-0402-L_1_0_1-W_0_5_0_1-IPC_C]
C27  0.1uF_25V_0402  [FP-0402-L_1_0_1-W_0_5_0_1-IPC_C]
C54  0.1uF_50V_0402  [FP-C1005-050-0_05-IPC_C]
C56  10uF_25V_0603  [FP-CL10-IPC_C]
C57  0.1uF_50V_0402  [FP-C1005-050-0_05-IPC_C]
FB2  742792641  [FP-742792641-MFG]
L2  742792780  [SMD-0402]
R3  100_1%_0402  [RESC1005X40X25ML05T10]
R7  49.9_1%_0402  [RESC1005X40X25NL10T10]
R8  100_1%_0402  [RESC1005X40X25ML05T10]
R26  49.9_1%_0402  [RESC1005X40X25NL10T10]
R27  4.7K_1%_0402  [RESC1005X40X25NL10T10]
R28  4.7K_1%_0402  [RESC1005X40X25NL10T10]
R29  4.7K_1%_0402  [RESC1005X40X25NL10T10]
R95  4.7K_1%_0402  [RESC1005X40X25NL10T10]
R96  4.7K_1%_0402  [RESC1005X40X25NL10T10]
Y1  SIT5001AC-3E-33N0-40.000000X  [FP-SiT5001-3-MFG]
Y4  SiTime_SiT5501AC-WU-33E0-10T  [SITIME_SPL-086-CQFN-010-C07050_REV_DRAFT]

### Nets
GND: C22.2 C23.2 C24.2 C25.2 C26.2 C27.2 C54.1 C56.2 C57.1 R8.1 Y1.2(GND) Y4.5(GND)
P3V3: C22.1 C23.1 C54.2 FB2.2 L2.1 R3.2 R28.2 R29.2 R95.2 R96.2
DPLL_OSCI: C21.2 ; off-sheet DPLL_OSCI
SiT5501_PLL_SCL: R96.1 Y4.3(NC) ; off-sheet SiT5501_PLL_SCL
SiT5501_PLL_SDA: R95.1 Y4.2(NC) ; off-sheet SiT5501_PLL_SDA
TCXO_10M: R26.1 ; off-sheet TCXO_10M
NetC21_1: C21.1 R3.1 R7.2 R8.2
NetC24_1: C24.1 C25.1 C26.1 C27.1 L2.2 Y1.4(VDD)
NetC56_1: C56.1 C57.2 FB2.1 R27.1 Y4.10(VDD)
NetR7_1: R7.1 Y1.3(OUT)
NetR26_2: R26.2 Y4.6(CLK)
NetR27_2: R27.2 Y4.1(OE)
NetR28_1: R28.1 Y4.7(NC)
NetR29_1: R29.1 Y4.8(NC)

Not connected (* = marked no-connect by the designer): Y1 1(NC); Y4 4(NC) 9(NC)

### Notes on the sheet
- 10MHz Source for DPLL

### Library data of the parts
C21 C23 C25-C27 = CMP-2008-02519-2: as C55 on sheet 03-8A34004_DPLL-1
C22 C24 = CMP-13271-000002-1: as C9 on sheet 02-WWVB_Path
C54 C57 = CMP-2000-05393-2: Multilayer Ceramic Capacitors 100nF ±10% 50V X7R SMD 0402
C56 = CMP-13271-004224-1: Cap Ceramic 10uF 25V X5R ±20% Pad SMD 0603 +85°C T/R
FB2 = CMP-0220-00171-2: FERRITE BEAD 300 OHM 0603 1LN; Inductance: 18nH; Max DC Current: 2A; Number of Lines: 1; Test Frequency: 100MHz; Impedance: 300R; DC Resistance (DCR): 150mR; Tolerance: 25%
L2 = CMP-0220-00137-1: as L3 on sheet 04-8A34004_DPLL-2
R3 R8 = CMP-2002-06458-1: as R4 on sheet 02-WWVB_Path
R7 R26 = CMP-2002-04448-1: Part Number: RK73H1ETTP49R9F; Manufacturer: KOA Speer
R27-R29 R95 R96 = CMP-2002-05217-1: as R18 on sheet 03-8A34004_DPLL-1
Y1 = CMP-25159-259584-1: MEMS OSC TCXO 40.0000MHZ LVCMOS; Frequency Stability: 5ppm; Max Supply Current: 33mA; Frequency: 40MHz
Y4 = CMP-OSC-00029-2: OSC, MEMS, STRATUM 3E, 10.000MHZ, 10PPB STAB, LVCMOS, 3.3V, O/P EN, 7.0X5.0X2.2MM, CQFN-10; Manufacturer Part Number: SiT5501AI-WU033JH-10.000000; Manufacturer: SiTime; Frequency: 10 MHz

## Sheet 06-RP2040.SchDoc
size B; SheetNumber: 6; SheetTotal: 8
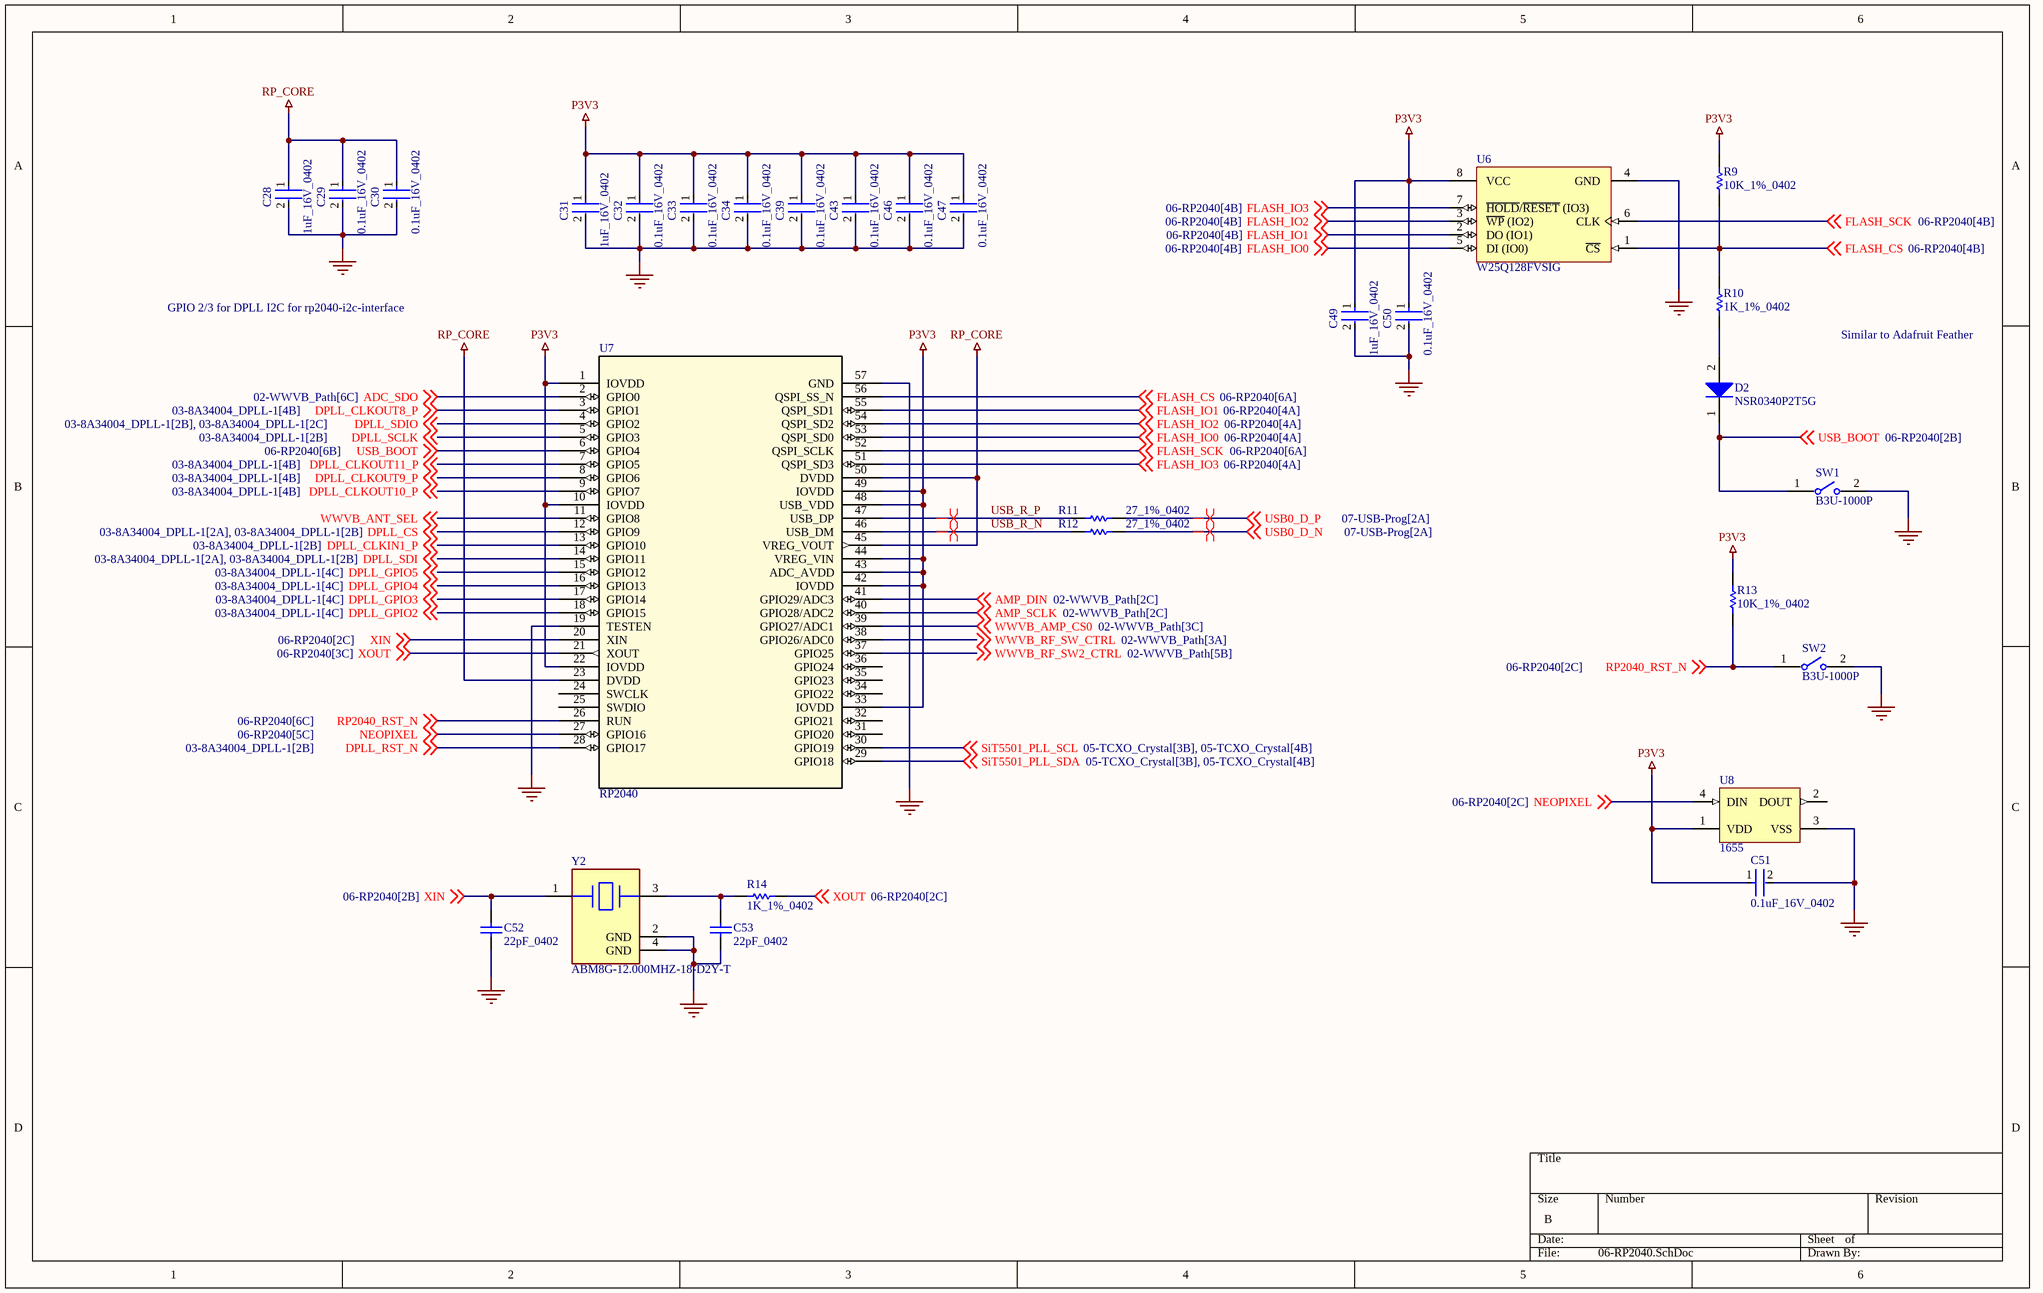
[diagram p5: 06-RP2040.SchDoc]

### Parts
C28  1uF_16V_0402  [FP-0402-L_1_0_0_05-W_0_5-IPC_A]
C29  0.1uF_16V_0402  [FP-C0402-BB-MFG]
C30  0.1uF_16V_0402  [FP-C0402-BB-MFG]
C31  1uF_16V_0402  [FP-0402-L_1_0_0_05-W_0_5-IPC_A]
C32  0.1uF_16V_0402  [FP-C0402-BB-MFG]
C33  0.1uF_16V_0402  [FP-C0402-BB-MFG]
C34  0.1uF_16V_0402  [FP-C0402-BB-MFG]
C39  0.1uF_16V_0402  [FP-C0402-BB-MFG]
C43  0.1uF_16V_0402  [FP-C0402-BB-MFG]
C46  0.1uF_16V_0402  [FP-C0402-BB-MFG]
C47  0.1uF_16V_0402  [FP-C0402-BB-MFG]
C49  1uF_16V_0402  [FP-0402-L_1_0_0_05-W_0_5-IPC_A]
C50  0.1uF_16V_0402  [FP-C0402-BB-MFG]
C51  0.1uF_16V_0402  [FP-C0402-BB-MFG]
C52  22pF_0402  [CAPC1005X55X25ML05T05]
C53  22pF_0402  [CAPC1005X55X25ML05T05]
D2  NSR0340P2T5G  [ONSC-SOD-923-2-514AB-01_B_V]
R9  10K_1%_0402  [RESC1005X40X25NL10T10]
R10  1K_1%_0402  [RESC1005X40X25LL10T10]
R11  27_1%_0402  [RESC1005X40X25LL05T10]
R12  27_1%_0402  [RESC1005X40X25LL05T10]
R13  10K_1%_0402  [RESC1005X40X25NL10T10]
R14  1K_1%_0402  [RESC1005X40X25LL10T10]
SW1  B3U-1000P  [FP-B3U-1000P-MFG]
SW2  B3U-1000P  [FP-B3U-1000P-MFG]
U6  W25Q128FVSIG  [WINB-SOIC-8_M]
U7  RP2040  [IC57_RP2040]
U8  1655  [ADA-RGB-1655_V]
Y2  ABM8G-12.000MHZ-18-D2Y-T  [FP-ABM8G-MFG]

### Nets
GND: C28.2 C29.2 C30.2 C31.2 C32.2 C33.2 C34.2 C39.2 C43.2 C46.2 C47.2 C49.2 C50.2 C51.2 C52.1 C53.1 SW1.2 SW2.2 U6.4(GND) U7.19(TESTEN) U7.57(GND) U8.3(VSS) Y2.2(GND) Y2.4(GND)
P3V3: C31.1 C32.1 C33.1 C34.1 C39.1 C43.1 C46.1 C47.1 C49.1 C50.1 C51.1 R9.1 R13.1 U6.8(VCC) U7.1(IOVDD) U7.10(IOVDD) U7.22(IOVDD) U7.33(IOVDD) U7.42(IOVDD) U7.43(ADC_AVDD) U7.44(VREG_VIN) U7.48(USB_VDD) U7.49(IOVDD) U8.1(VDD)
RP_CORE: C28.1 C29.1 C30.1 U7.23(DVDD) U7.45(VREG_VOUT) U7.50(DVDD)
ADC_SDO: U7.2(GPIO0) ; off-sheet ADC_SDO
AMP_DIN: U7.41(GPIO29/ADC3) ; off-sheet AMP_DIN
AMP_SCLK: U7.40(GPIO28/ADC2) ; off-sheet AMP_SCLK
DPLL_CLKIN1_P: U7.13(GPIO10) ; off-sheet DPLL_CLKIN1_P
DPLL_CLKOUT8_P: U7.3(GPIO1) ; off-sheet DPLL_CLKOUT8_P
DPLL_CLKOUT9_P: U7.8(GPIO6) ; off-sheet DPLL_CLKOUT9_P
DPLL_CLKOUT10_P: U7.9(GPIO7) ; off-sheet DPLL_CLKOUT10_P
DPLL_CLKOUT11_P: U7.7(GPIO5) ; off-sheet DPLL_CLKOUT11_P
DPLL_CS: U7.12(GPIO9) ; off-sheet DPLL_CS
DPLL_GPIO2: U7.18(GPIO15) ; off-sheet DPLL_GPIO2
DPLL_GPIO3: U7.17(GPIO14) ; off-sheet DPLL_GPIO3
DPLL_GPIO4: U7.16(GPIO13) ; off-sheet DPLL_GPIO4
DPLL_GPIO5: U7.15(GPIO12) ; off-sheet DPLL_GPIO5
DPLL_RST_N: U7.28(GPIO17) ; off-sheet DPLL_RST_N
DPLL_SCLK: U7.5(GPIO3) ; off-sheet DPLL_SCLK
DPLL_SDI: U7.14(GPIO11) ; off-sheet DPLL_SDI
DPLL_SDIO: U7.4(GPIO2) ; off-sheet DPLL_SDIO
FLASH_CS: R9.2 R10.2 U6.1(~{CS}) U7.56(QSPI_SS_N) ; off-sheet FLASH_CS
FLASH_IO0: U6.5(DI_(IO0)) U7.53(QSPI_SD0) ; off-sheet FLASH_IO0
FLASH_IO1: U6.2(DO_(IO1)) U7.55(QSPI_SD1) ; off-sheet FLASH_IO1
FLASH_IO2: U6.3(~{WP}_(IO2)) U7.54(QSPI_SD2) ; off-sheet FLASH_IO2
FLASH_IO3: U6.7(~{HOLD}/~{RESET}_(IO3)) U7.51(QSPI_SD3) ; off-sheet FLASH_IO3
FLASH_SCK: U6.6(CLK) U7.52(QSPI_SCLK) ; off-sheet FLASH_SCK
NEOPIXEL: U7.27(GPIO16) U8.4(DIN) ; off-sheet NEOPIXEL
RP2040_RST_N: R13.2 SW2.1 U7.26(RUN) ; off-sheet RP2040_RST_N
SiT5501_PLL_SCL: U7.30(GPIO19) ; off-sheet SiT5501_PLL_SCL
SiT5501_PLL_SDA: U7.29(GPIO18) ; off-sheet SiT5501_PLL_SDA
USB0_D_N: R12.2 ; off-sheet USB0_D_N
USB0_D_P: R11.2 ; off-sheet USB0_D_P
USB_BOOT: D2.1(K) SW1.1 U7.6(GPIO4) ; off-sheet USB_BOOT
USB_R_N: R12.1 U7.46(USB_DM)
USB_R_P: R11.1 U7.47(USB_DP)
WWVB_AMP_CS0: U7.39(GPIO27/ADC1) ; off-sheet WWVB_AMP_CS0
WWVB_ANT_SEL: U7.11(GPIO8) ; off-sheet WWVB_ANT_SEL
WWVB_RF_SW2_CTRL: U7.37(GPIO25) ; off-sheet WWVB_RF_SW2_CTRL
WWVB_RF_SW_CTRL: U7.38(GPIO26/ADC0) ; off-sheet WWVB_RF_SW_CTRL
XIN: C52.2 U7.20(XIN) Y2.1 ; off-sheet XIN
XOUT: R14.2 U7.21(XOUT) ; off-sheet XOUT
NetC53_2: C53.2 R14.1 Y2.3
NetD2_2: D2.2(A) R10.1

Not connected (* = marked no-connect by the designer): U7 24(SWCLK) 25(SWDIO) 31(GPIO20) 32(GPIO21) 34(GPIO22) 35(GPIO23) 36(GPIO24); U8 2(DOUT)

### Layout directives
differential pair: USB0_D_N, USB0_D_P, USB_R_N, USB_R_P

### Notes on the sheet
- GPIO 2/3 for DPLL I2C for rp2040-i2c-interface
- Similar to Adafruit Feather

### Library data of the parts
C28 C31 C49 = CMP-14477-000104-2: as C8 on sheet 02-WWVB_Path
C29 C30 C32-C34 C39 C43 C46 C47 C50 C51 = CMP-1034-02068-3: as C3 on sheet 02-WWVB_Path
C52 C53 = CMP-2100-03590-1: Chip Capacitor, 22 pF, +/- 5%, 50 V, -55 to 125 degC, 0402 (1005 Metric), RoHS, Tape and Reel; Manufacturer: Yageo; Voltage Rating: 50V; Dielectric Material: Ceramic; Capacitance: 22pF; Temperature Coefficient: 30ppm/degC; Dielectric: C0G; Insulation Resistance: 100GR
D2 = CMP-1055-00495-1: Schottky Barrier Diode, 2-Pin SOD-923, Pb-Free, Tape and Reel; Manufacturer: On Semiconductor; Configuration: Single; IFSM Max (A): 1
R9 R13 = CMP-2002-04694-1: Manufacturer: Bourns; Part Number: CR0402-FX-1002GLF
R10 R14 = CMP-2002-04692-1: Part Number: CR0402-FX-1001GLF; Manufacturer: Bourns
R11 R12 = CMP-2002-07055-1: Part Number: RC0402FR-0727RL; Manufacturer: Yageo / Phycomp
SW1 SW2 = CMP-2100-03586-2: SWITCH TACTILE SPST-NO 0.05A 12V; Contact Resistance: 100mR; Operating Force: 1.5N; Max Current Rating: 50mA; Switch Travel: 0.15mm; Actuator Type: Standard; Mechanical Life: 200000Cycles; Ratings: Dust Proof; Illumination Type: Non-Illuminated; Throw Configuration: SPST; Actuator Length: 0.4mm; Switch Function: Off-Mom
U6 = CMP-2000-05005-1: 3V 128M-Bit Serial Flash Memory with Dual/Quad SPI & QPI, 2.7 to 3.6 V, -40 to 85 degC, 8-Pin SOIC, RoHS, Tape and Reel; Manufacturer: Winbond; Number of Words: 16777216; Address Bus: 24b; Word Size: 8b; Boot Type: NotRequired; Supply Current: 20mA; Operating Supply Voltage (Max): 3.6V; Sync/Async: Synchronous; Rad Hardened: No; Interface Type: Serial(SPI); Access Time (Max): 7ns; Operating Supply Voltage (Min): 2.7V; Operating Supply Voltage (Typ): 3/3.3V; Programmable: Yes; Density: 134217728Bit; Cell Type: NOR
U7 = RP2040: No Description Available; Mfr_Name: Raspberry Pi
U8 = CMP-2000-05026-1: Intelligent Control LED Integrated Light Source, 3.5 to 5.3 V, -25 to 80 degC, 4-Pin SMD, RoHS, Tape and Reel; Manufacturer: Adafruit-Industries-LLC; Number of LEDs: 10; Configuration: Discrete; Utilized LED: WS2812(5050)
Y2 = CMP-2000-05039-3: Crystal 12MHz ±20ppm (Tol) ±30ppm (Stability) 18pF FUND 120Ω 4-Pin SMD T/R; Series Resistance: 120R

## Sheet 07-USB-Prog.SchDoc
size B; SheetNumber: 7; SheetTotal: 7
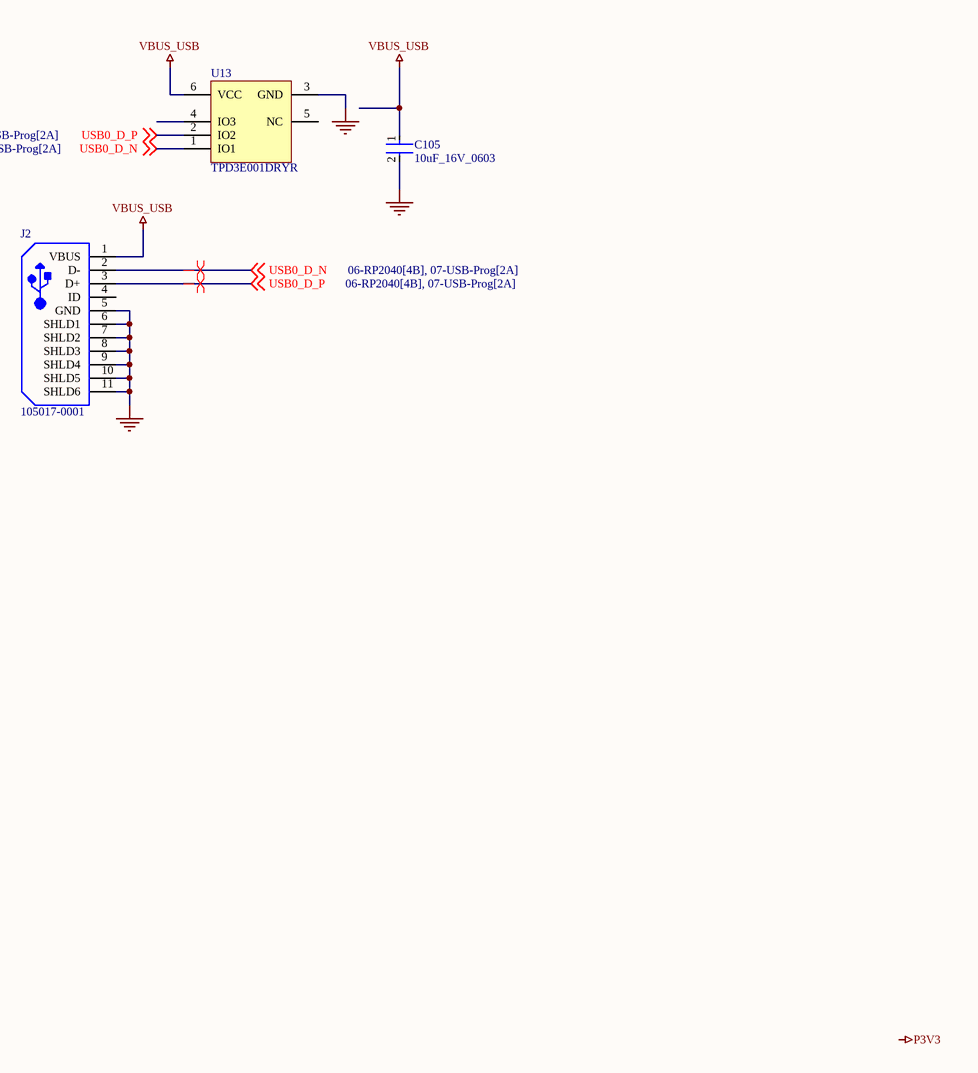
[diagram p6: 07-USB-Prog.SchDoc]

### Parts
C105  10uF_16V_0603  [FP-0603-L_1_6_0_2-W_0_8_0-MFG]
J2  105017-0001  [USB-MICRO-B_V]
U13  TPD3E001DRYR  [DRY0006A]

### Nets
GND: C105.2 J2.5(GND) J2.6(SHLD1) J2.7(SHLD2) J2.8(SHLD3) J2.9(SHLD4) J2.10(SHLD5) J2.11(SHLD6) U13.3(GND)
VBUS_USB: C105.1 J2.1(VBUS) U13.6(VCC)
USB0_D_N: J2.2(D-) U13.1(IO1) ; off-sheet USB0_D_N
USB0_D_P: J2.3(D+) U13.2(IO2) ; off-sheet USB0_D_P

Not connected (* = marked no-connect by the designer): J2 4(ID); U13 4(IO3) 5(NC)

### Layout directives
differential pair: USB0_D_N, USB0_D_P

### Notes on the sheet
- Labels drawn without touching a wire or pin: P3V3

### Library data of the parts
C105 = CMP-2000-06226-4: Multilayer Ceramic Capacitor 10uF 16V X5R 20% SMD 0603 T/R
J2 = CMP-2000-05827-1: Micro-USB B Receptacle, Right Angle, Bottom Mount, Surface Mount, with Solder Tabs, -30 to 85 degC, 5-Pin USB, RoHS, Tape and Reel; Manufacturer: Molex; Featured Product: Micro-USBConnectorsUSBConnectors; Other Names: WM1399DKR; Package Version: Rev. F, 12/2012; Number of Contacts: 5; Connector Type: USB-microB; Catalog Drawings: 1050170001; 3D Model: 105017-0001.stp; Mating Products: WM17145-ND-CABLEMICROUSBBTOSTDA1.0MWM17147-ND-CABLEMICROUSBBTOSTDA2.0MWM17146-ND-CABLEMICROUSBBTOSTDA1.5M; PCN Assembly/Origin: ResinSupplier21/Oct/2015; Voltage - Max: 30V; Online Catalog: Molex-MicroUSB
U13 = CMP-0326-00032-3: Low-Capacitance + / - 15 kV ESD-Protection Array for High-Speed Data Interfaces, 3 Channels, -40 to +85 degC, 6-pin SON (DRY), Green (RoHS & no Sb/Br); Manufacturer: Texas Instruments; USB High Speed: TRUE; SubFamily: ESD Solution; IO Capacitance(Typ)(pF): 1.5; IEC 61000-4-2 Contact(+/- kV): 8; IO Leakage Current(nA): Jan-00; Breakdown Voltage(Min)(V): 11; IEC 61000-4-2 Air-Gap(+/- kV): 15

## Sheet 08-Power.SchDoc
size B; SheetNumber: 8; SheetTotal: 8
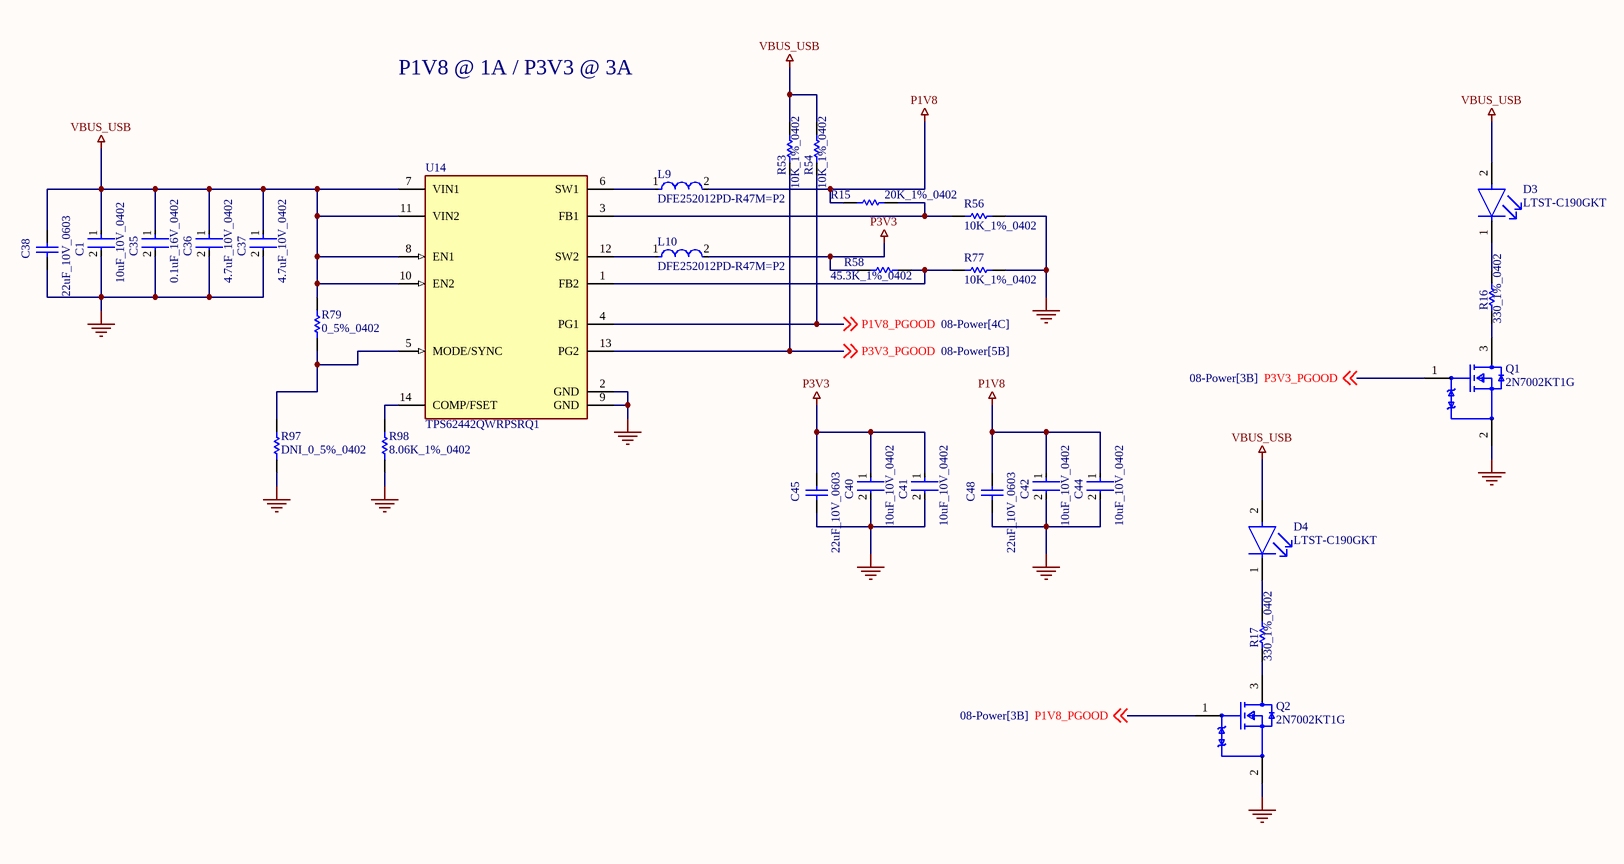
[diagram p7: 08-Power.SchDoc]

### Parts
C1  10uF_10V_0402  [FP-CL05A106MP5NUNC-MFG]
C35  0.1uF_16V_0402  [FP-C0402-BB-MFG]
C36  4.7uF_10V_0402  [FP-C1005-050-0_15-MFG]
C37  4.7uF_10V_0402  [FP-C1005-050-0_15-MFG]
C38  22uF_10V_0603  [CAPC1608X100X20ML10]
C40  10uF_10V_0402  [FP-CL05A106MP5NUNC-MFG]
C41  10uF_10V_0402  [FP-CL05A106MP5NUNC-MFG]
C42  10uF_10V_0402  [FP-CL05A106MP5NUNC-MFG]
C44  10uF_10V_0402  [FP-CL05A106MP5NUNC-MFG]
C45  22uF_10V_0603  [CAPC1608X100X20ML10]
C48  22uF_10V_0603  [CAPC1608X100X20ML10]
D3  LTST-C190GKT  [FP-LTST-C190GKT-MFG]
D4  LTST-C190GKT  [FP-LTST-C190GKT-MFG]
L9  DFE252012PD-R47M=P2  [FP-DFE252012C-IPC_A]
L10  DFE252012PD-R47M=P2  [FP-DFE252012C-IPC_A]
Q1  2N7002KT1G  [FP-318-08-MFG]
Q2  2N7002KT1G  [FP-318-08-MFG]
R15  20K_1%_0402  [RESC1005X40X25ML10T10]
R16  330_1%_0402  [RESC1005X40X25NL10T10]
R17  330_1%_0402  [RESC1005X40X25NL10T10]
R53  10K_1%_0402  [RESC1005X40X25NL10T10]
R54  10K_1%_0402  [RESC1005X40X25NL10T10]
R56  10K_1%_0402  [RESC1005X40X25NL10T10]
R58  45.3K_1%_0402  [RESC0402(1005)_L]
R77  10K_1%_0402  [RESC1005X40X25NL10T10]
R79  0_5%_0402  [RESC1005X40X25NL05T10]
R97  DNI_0_5%_0402  [RESC1005X40X25NL05T10]  (no BOM)
R98  8.06K_1%_0402  [RESC1005X40X25ML05T05]
U14  TPS62442QWRPSRQ1  [FP-RQR0014A-MFG]

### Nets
GND: C1.2 C35.2 C36.2 C37.2 C38.1 C40.2 C41.2 C42.2 C44.2 C45.1 C48.1 Q1.2(Source) Q2.2(Source) R56.1 R77.1 R97.1 R98.1 U14.2(GND) U14.9(GND)
P1V8: C42.1 C44.1 C48.2 L9.2 R15.1
P3V3: C40.1 C41.1 C45.2 L10.2 R58.1
VBUS_USB: C1.1 C35.1 C36.1 C37.1 C38.2 D3.2(A) D4.2(A) R53.2 R54.2 R79.2 U14.7(VIN1) U14.8(EN1) U14.10(EN2) U14.11(VIN2)
P1V8_PGOOD: Q2.1(Gate) R54.1 U14.4(PG1) ; off-sheet P1V8_PGOOD
P3V3_PGOOD: Q1.1(Gate) R53.1 U14.13(PG2) ; off-sheet P3V3_PGOOD
NetD3_1: D3.1(C) R16.2
NetD4_1: D4.1(C) R17.2
NetL9_1: L9.1 U14.6(SW1)
NetL10_1: L10.1 U14.12(SW2)
NetQ1_3: Q1.3(Drain) R16.1
NetQ2_3: Q2.3(Drain) R17.1
NetR15_2: R15.2 R56.2 U14.3(FB1)
NetR58_2: R58.2 R77.2 U14.1(FB2)
NetR79_1: R79.1 R97.2 U14.5(MODE/SYNC)
NetR98_2: R98.2 U14.14(COMP/FSET)

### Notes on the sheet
- P1V8 @ 1A / P3V3 @ 3A

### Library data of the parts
C1 C40-C42 C44 = CMP-13271-000002-1: as C9 on sheet 02-WWVB_Path
C35 = CMP-1034-02068-3: as C3 on sheet 02-WWVB_Path
C36 C37 = CMP-2000-05997-2: as C10 on sheet 02-WWVB_Path
C38 C45 C48 = CMP-2000-05441-1: Chip Capacitor, 22 uF, +/- 20%, 10 V, -55 to 85 degC, 0603 (1608 Metric), RoHS, Tape and Reel; Manufacturer: TDK; PCN Part Number: MLCCPartNumberChange30/Nov/2012; Voltage - Rated: 10V; Product Training Modules: CSeriesGeneralApplicationsSEAT,CCV,andTVCLDesignToolsGuidetoReplacinganElectrolyticCapacitorwithanMLCC; Other Names: 445-9077-1; Design Resources: 20WNon-IsolatedBuckLEDDriverUsingPLLNK460KG; Online Catalog: CSeries,GeneralPurpose; Capacitance: 22µF; Temperature Coefficient: X5R; Kits: 445-9014-KIT-ND-KITMLCC100PF-22UF060310-50V
D3 D4 = CMP-22017-000005-2: as D1 on sheet 03-8A34004_DPLL-1
L9 L10 = CMP-06042-015149-1: Shielded Wirewound Inductor 0.47uH 20% 4000mA 0.027Ω 1008 (2520)
Q1 Q2 = CMP-1058-00766-2: MOSFET N-CH 60V 320MA SOT-23; Max Power Dissipation: 420mW; Nominal Vgs: 2.3V; Fall Time: 9ns; Turn-Off Delay Time: 55.8ns; Number of Elements: 1; Rds On Max: 1.6R; Input Capacitance: 24.5pF; Turn-On Delay Time: 12.2ns; Element Configuration: Single; Gate to Source Voltage (Vgs): 20V; Power Dissipation: 300mW
R15 = CMP-2002-05709-1: Manufacturer: TE Connectivity / AMP; Part Number: CRG0402F20K
R16 R17 = CMP-2002-05853-1: as R71 on sheet 03-8A34004_DPLL-1
R53 R54 R56 R77 = CMP-2002-04694-1: as R9 on sheet 06-RP2040
R58 = CMP-1011-00697-1: 45K3 0.063W 1% 0402 (1005 Metric)  SMD; Case-EIA: 0402; Case-Metric: 1005; Value: 45300.00 Ohm
R79 R97 = CMP-2002-06457-1: as R6 on sheet 02-WWVB_Path
R98 = CMP-2002-00253-3: Chip Resistor, 8.06 KOhm, +/- 1%, 63 mW, -55 to 155 degC, 0402 (1005 Metric), RoHS, Tape and Reel; PartNumber: CRCW04028K06FKED; Manufacturer: Basic Passives; Case\/Package: 0402; Power Rating: 63 mW; Voltage Rating: 50 V
U14 = CMP-04918-000654-1: Adjustable-Frequency Dual Step-Down Converter, 2.7-6V VIN, 0.6-5.5V 2A VOUT, VQFN-HR14

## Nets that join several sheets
DPLL_VDD_CLK: 03-8A34004_DPLL-1 (U11.48), 04-8A34004_DPLL-2 (C94.1 C95.1 L11.2)
DPLL_VDD_DCO_Q8: 03-8A34004_DPLL-1 (U11.38), 04-8A34004_DPLL-2 (C62.1 C63.1 L4.2)
DPLL_VDD_DCO_Q9: 03-8A34004_DPLL-1 (U11.31), 04-8A34004_DPLL-2 (C77.1 C78.1 L5.2)
DPLL_VDD_DCO_Q10: 03-8A34004_DPLL-1 (U11.30), 04-8A34004_DPLL-2 (C87.1 C88.1 L7.2)
DPLL_VDD_DCO_Q11: 03-8A34004_DPLL-1 (U11.23), 04-8A34004_DPLL-2 (C97.1 C98.1 L12.2)
DPLL_VDD_DIG: 03-8A34004_DPLL-1 (U11.6), 04-8A34004_DPLL-2 (5 pins)
DPLL_VDD_GPIO: 03-8A34004_DPLL-1 (U11.13), 04-8A34004_DPLL-2 (5 pins)
DPLL_VDDA_BG_LC: 03-8A34004_DPLL-1 (U11.15 U11.16), 04-8A34004_DPLL-2 (C68.1 C69.1 C70.1 L3.2)
DPLL_VDDA_FB: 03-8A34004_DPLL-1 (U11.47), 04-8A34004_DPLL-2 (C109.1 C110.1 L15.2)
DPLL_VDDA_PDCP_XTAL: 03-8A34004_DPLL-1 (U11.46), 04-8A34004_DPLL-2 (C84.1 C85.1 L6.2)
DPLL_VDDO_Q8: 03-8A34004_DPLL-1 (U11.39), 04-8A34004_DPLL-2 (C102.1 C103.1 L13.2)
DPLL_VDDO_Q9: 03-8A34004_DPLL-1 (U11.35), 04-8A34004_DPLL-2 (C92.1 C93.1 L8.2)
DPLL_VDDO_Q10: 03-8A34004_DPLL-1 (U11.26), 04-8A34004_DPLL-2 (C114.1 C115.1 L16.2)
DPLL_VDDO_Q11: 03-8A34004_DPLL-1 (U11.22), 04-8A34004_DPLL-2 (C107.1 C108.1 L14.2)
GND: 01-Antennas (5 pins), 02-WWVB_Path (27 pins), 03-8A34004_DPLL-1 (20 pins), 04-8A34004_DPLL-2 (53 pins), 05-TCXO_Crystal (12 pins), 06-RP2040 (24 pins), 07-USB-Prog (9 pins), 08-Power (19 pins)
P1V8: 04-8A34004_DPLL-2 (13 pins), 08-Power (5 pins)
P3V3: 02-WWVB_Path (11 pins), 03-8A34004_DPLL-1 (13 pins), 04-8A34004_DPLL-2 (21 pins), 05-TCXO_Crystal (10 pins), 06-RP2040 (24 pins), 08-Power (5 pins)
VBUS_USB: 02-WWVB_Path (6 pins), 07-USB-Prog (C105.1 J2.1 U13.6), 08-Power (14 pins)
ADC_SDO: 02-WWVB_Path (U5.2), 06-RP2040 (U7.2)
AMP_DIN: 02-WWVB_Path (U4.2), 06-RP2040 (U7.41)
AMP_SCLK: 02-WWVB_Path (U4.1), 06-RP2040 (U7.40)
DPLL_CLKIN1_P: 03-8A34004_DPLL-1 (R36.1), 06-RP2040 (U7.13)
DPLL_CLKOUT8_N: 02-WWVB_Path (U5.1), 03-8A34004_DPLL-1 (R33.2)
DPLL_CLKOUT8_P: 03-8A34004_DPLL-1 (R39.2), 06-RP2040 (U7.3)
DPLL_CLKOUT9_N: 02-WWVB_Path (U5.3), 03-8A34004_DPLL-1 (R35.2)
DPLL_CLKOUT9_P: 03-8A34004_DPLL-1 (R40.2), 06-RP2040 (U7.8)
DPLL_CLKOUT10_P: 03-8A34004_DPLL-1 (R41.2), 06-RP2040 (U7.9)
DPLL_CLKOUT11_P: 03-8A34004_DPLL-1 (R42.2), 06-RP2040 (U7.7)
DPLL_CS: 03-8A34004_DPLL-1 (R46.1 U11.9), 06-RP2040 (U7.12)
DPLL_GPIO2: 03-8A34004_DPLL-1 (U11.29), 06-RP2040 (U7.18)
DPLL_GPIO3: 03-8A34004_DPLL-1 (U11.19), 06-RP2040 (U7.17)
DPLL_GPIO4: 03-8A34004_DPLL-1 (U11.37), 06-RP2040 (U7.16)
DPLL_GPIO5: 03-8A34004_DPLL-1 (U11.36), 06-RP2040 (U7.15)
DPLL_OSCI: 03-8A34004_DPLL-1 (U11.45), 05-TCXO_Crystal (C21.2)
DPLL_RST_N: 03-8A34004_DPLL-1 (R31.1 U11.17), 06-RP2040 (U7.28)
DPLL_SCLK: 03-8A34004_DPLL-1 (R49.1 U11.12), 06-RP2040 (U7.5)
DPLL_SDI: 03-8A34004_DPLL-1 (R45.1 U11.10), 06-RP2040 (U7.14)
DPLL_SDIO: 03-8A34004_DPLL-1 (R50.1 U11.11), 06-RP2040 (U7.4)
SiT5501_PLL_SCL: 05-TCXO_Crystal (R96.1 Y4.3), 06-RP2040 (U7.30)
SiT5501_PLL_SDA: 05-TCXO_Crystal (R95.1 Y4.2), 06-RP2040 (U7.29)
TCXO_10M: 03-8A34004_DPLL-1 (U11.1), 05-TCXO_Crystal (R26.1)
USB0_D_N: 06-RP2040 (R12.2), 07-USB-Prog (J2.2 U13.1)
USB0_D_P: 06-RP2040 (R11.2), 07-USB-Prog (J2.3 U13.2)
WWVB_AMP_CS0: 02-WWVB_Path (U4.10), 06-RP2040 (U7.39)
WWVB_RF_IN: 01-Antennas (D5.2 J4.1), 02-WWVB_Path (C2.1)
WWVB_RF_SW2_CTRL: 02-WWVB_Path (U2.4), 06-RP2040 (U7.37)
WWVB_RF_SW_CTRL: 02-WWVB_Path (U1.4), 06-RP2040 (U7.38)

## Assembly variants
845-XXXXX_PCBA_projectname: all parts fitted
